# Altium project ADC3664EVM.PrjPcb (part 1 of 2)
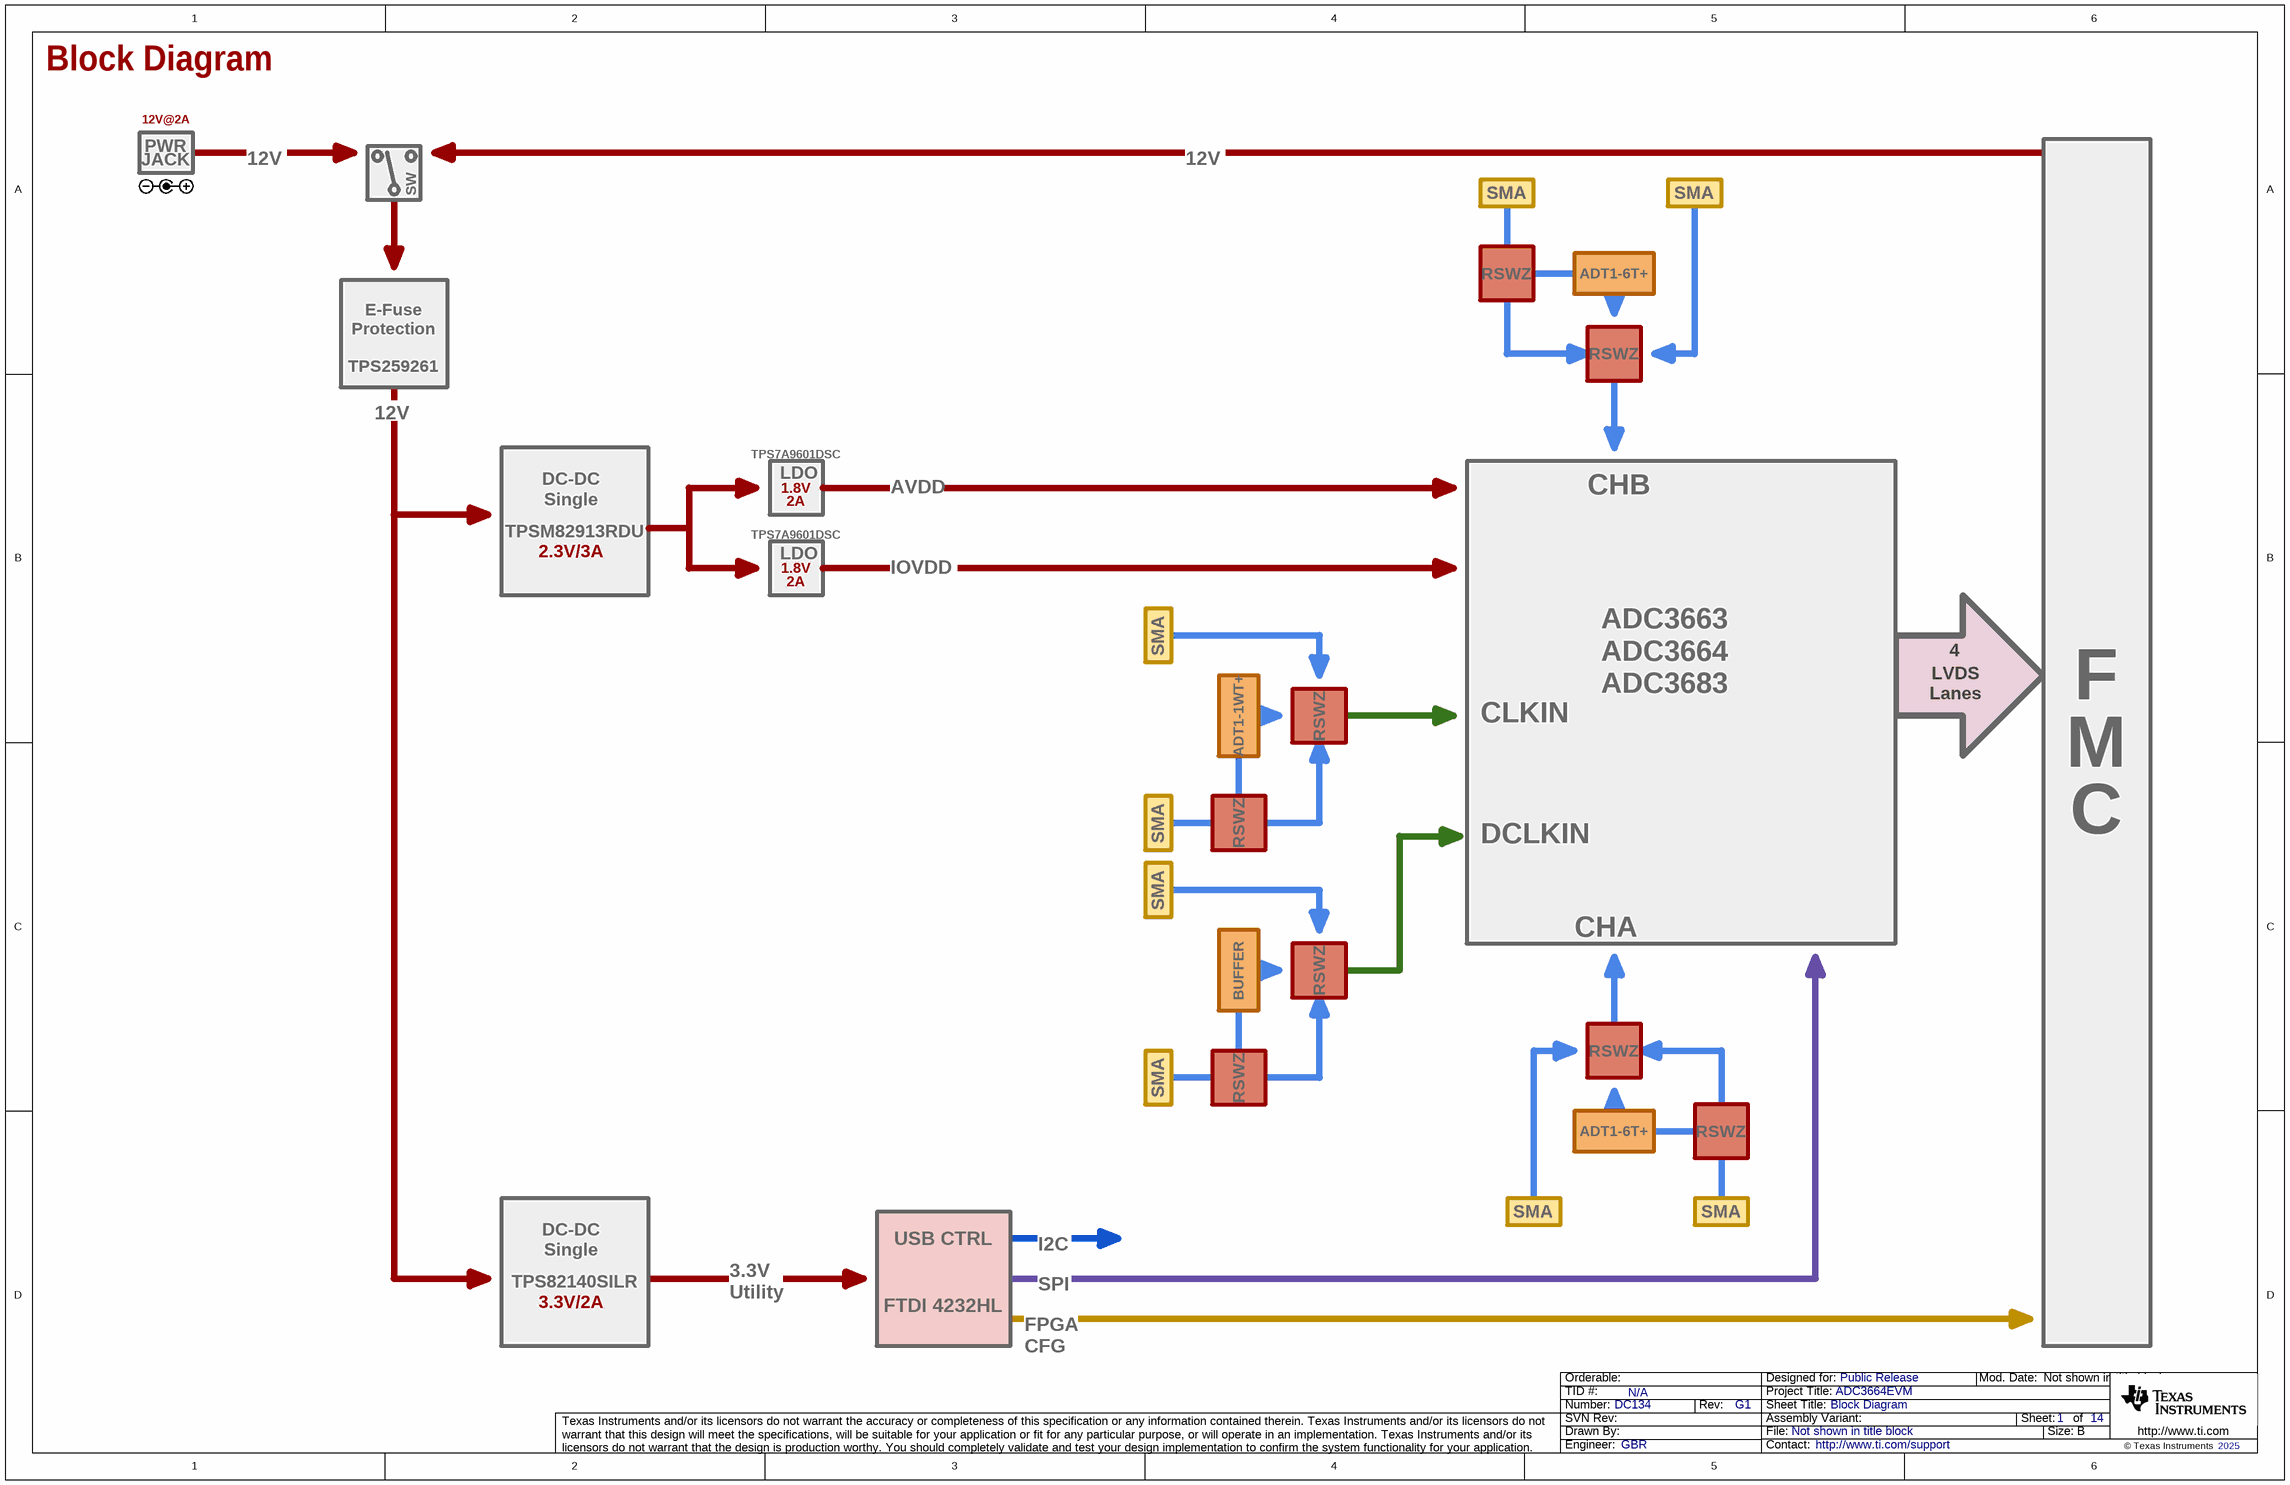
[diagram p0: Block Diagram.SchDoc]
TID: N/A; TechSupport: http://www.ti.com/support; SCH_Rev: G1; PRJ_Title: ADC3664EVM; PRJ_Number: DC134; PRJ_Engineer: GBR; PRJ_Customer: Public Release; PCB_Rev: G1; PCB_Layout: GBR; CopyrightYear: 2025
14 sheets, 374 parts. Net scope: flat (ports and power ports of the same name join across sheets).
Board file: ADC3664EVM.PcbDoc
Sheets:
  Block Diagram.SchDoc
  12V Input, Efuse and 3p3V Utility.SchDoc
  Power DC-DC.SchDoc
  Power LDO.SchDoc
  Power Sense ADC.SchDoc
  USB Control FTDI.SchDoc
  Comms LVL Shift and MUX.SchDoc
  CLK and DCLKIN.SchDoc
  ADC Inputs.SchDoc
  DUT IO.SchDoc
  FMC+ Sections A-E.SchDoc
  FMC+ Sections F-H, J, K.SchDoc
  Hardware & Mechanicals.SchDoc
  Revision History.SchDoc

## Sheet Block Diagram.SchDoc: Block Diagram
size 431 x 279 mm; Date: Not shown in title block; ApprovedBy: Not shown in title block; CheckedBy: Not shown in title block; Author: Not shown in title block; CompanyName: Not shown in title block; Engineer: Not shown in title block; Organization: Not shown in title block; Address1: Not shown in title block; Address2: Not shown in title block; Address3: Not shown in title block; Address4: Not shown in title block; DocumentNumber: 1; Revision: Use project parameter SCH_Rev; SheetNumber: 1; SheetTotal: 14; PageSetup: Record=PageOptions¦CenterHorizontal=True¦CenterVertical=True¦PrintScale=1.00¦XCorrection=1.00¦YCorrection=1.00¦PrintKind=0¦BorderSize=5000000¦LeftOffset=0¦BottomOffset=0¦Orientation=2¦PaperLength=1000¦PaperWidth=1000¦Scale=100¦PaperSource=15¦PrintQuality=600¦MediaType=1¦DitherType=10¦PaperKind=Letter¦PrintScaleMode=1

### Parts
(Parts that share a designator on the sheet are numbered #1, #2 ... from top to bottom, then left to right.)
*#1  SMA  (graphical)
*#2  SMA  (graphical)
*#3  PartNum: RSWZ  (hidden comment: R-SWIZZLE)  (graphical)
*#4  PartNum: ADT1-6T+  (hidden comment: Balun)  (graphical)
*#5  PartNum: RSWZ  (hidden comment: R-SWIZZLE)  (graphical)
*#6  A_Value: 2A  V_Value: 1.8V  PartNum: TPS7A9601DSC  (hidden comment: LDO)  (graphical)
*#7  Limits: 2.3V/3A  PartNum: TPSM82913RDU  (hidden comment: DC-DC Single)  (graphical)
*#8  A_Value: 2A  V_Value: 1.8V  PartNum: TPS7A9601DSC  (hidden comment: LDO)  (graphical)
*#9  SMA  (graphical)
*#10  # Lanes: 4  (hidden comment: LVDS Lanes)  (graphical)
*#11  PartNum: ADT1-1WT+  (hidden comment: Balun)  (graphical)
*#12  PartNum: RSWZ  (hidden comment: R-SWIZZLE)  (graphical)
*#13  FMC  (value not drawn)  (graphical)
*#14  SMA  (graphical)
*#15  PartNum: RSWZ  (hidden comment: R-SWIZZLE)  (graphical)
*#16  SMA  (graphical)
*#17  PartNum: BUFFER  (hidden comment: Balun)  (graphical)
*#18  PartNum: RSWZ  (hidden comment: R-SWIZZLE)  (graphical)
*#19  PartNum: RSWZ  (hidden comment: R-SWIZZLE)  (graphical)
*#20  SMA  (graphical)
*#21  PartNum: RSWZ  (hidden comment: R-SWIZZLE)  (graphical)
*#22  PartNum: ADT1-6T+  (hidden comment: Balun)  (graphical)
*#23  PartNum: RSWZ  (hidden comment: R-SWIZZLE)  (graphical)
*#24  SMA  (graphical)
*#25  SMA  (graphical)
*#26  Limits: 3.3V/2A  PartNum: TPS82140SILR  (hidden comment: DC-DC Single)  (graphical)
*#27  FTDI 4232HL  (value not drawn)  (graphical)
*?#1  PartNum: 12V@2A  (hidden comment: Power Jack)  (graphical)
*?#2  SWITCH  (value not drawn)  (graphical)
*?#3  E-Fuse  (value not drawn)  (graphical)

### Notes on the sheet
- 12V
- AVDD
- CHB
- IOVDD
- ADC3663
  ADC3664
  ADC3683
- CLKIN
- DCLKIN
- CHA
- 3.3V
  Utility
- I2C
- SPI
- FPGA
  CFG

## Sheet 12V Input, Efuse and 3p3V Utility.SchDoc: 12V Input & 3.3V Utility
size 431 x 279 mm; Date: Not shown in title block; ApprovedBy: Not shown in title block; CheckedBy: Not shown in title block; Author: Not shown in title block; CompanyName: Not shown in title block; Engineer: Not shown in title block; Organization: Not shown in title block; Address1: Not shown in title block; Address2: Not shown in title block; Address3: Not shown in title block; Address4: Not shown in title block; DocumentNumber: 1; Revision: Use project parameter SCH_Rev; SheetNumber: 2; SheetTotal: 14; PageSetup: Record=PageOptions¦CenterHorizontal=True¦CenterVertical=True¦PrintScale=1.00¦XCorrection=1.00¦YCorrection=1.00¦PrintKind=0¦BorderSize=5000000¦LeftOffset=0¦BottomOffset=0¦Orientation=2¦PaperLength=1000¦PaperWidth=1000¦Scale=100¦PaperSource=15¦PrintQuality=600¦MediaType=1¦DitherType=10¦PaperKind=Letter¦PrintScaleMode=1
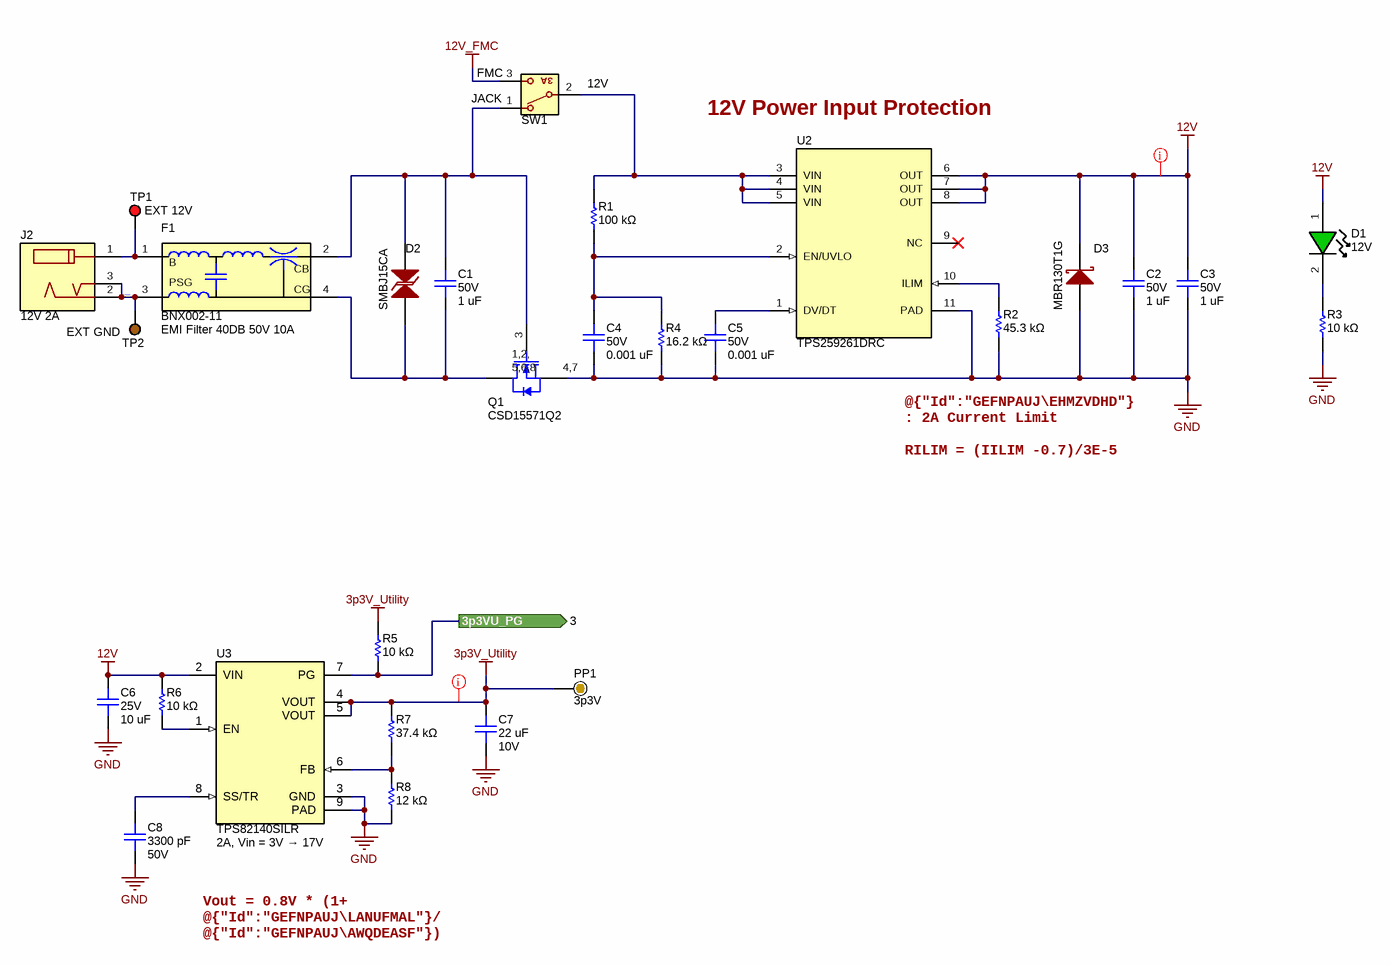
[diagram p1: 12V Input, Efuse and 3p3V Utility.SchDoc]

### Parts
C1  value 1 uF  Voltage - Rated: 50V  [0805L_cap]  (hidden comment: C2012X7R1H105K125AB)
C2  value 1 uF  Voltage - Rated: 50V  [0805L_cap]  (hidden comment: C2012X7R1H105K125AB)
C3  value 1 uF  Voltage - Rated: 50V  [0805L_cap]  (hidden comment: C2012X7R1H105K125AB)
C4  value 0.001 uF  Voltage - Rated: 50V  [0603L_cap]  (hidden comment: CGA3E2X7R1H102K080AA)
C5  value 0.001 uF  Voltage - Rated: 50V  [0603L_cap]  (hidden comment: CGA3E2X7R1H102K080AA)
C6  value 10 uF  Voltage - Rated: 25V  [0805L_cap]  (hidden comment: C2012X7S1E106K125AC)
C7  value 22 uF  Voltage - Rated: 10V  [0805L_cap]  (hidden comment: C2012X7S1A226M125AC)
C8  value 3300 pF  Voltage - Rated: 50V  [0402L_cap]  (hidden comment: CGA2B2X7R1H332K050BA)
D1  Text1: 12V  [LED_LTST-C190-Green]  (hidden comment: LTST-C191TGKT)
D2  SMBJ15CA  [SMBJ15CA]
D3  MBR130T1G  [SOD-123]
F1  BNX002-11  Text1: EMI Filter 40DB 50V 10A  [FIL_BNX002-11]
J2  Text1: 12V 2A  [RAPC722X]  (hidden comment: RAPC722X)
PP1  Text1: 3p3V  [ProbePoint_TH_40mil]  (hidden comment: Probe Point)  (no BOM)
Q1  CSD15571Q2  [DQK0006C]
R1  value 100 kΩ  [0402L]  (hidden comment: ERA-2AED104X)
R2  value 45.3 kΩ  [0402L]  (hidden comment: ERJ-2RKF4532X)
R3  value 10 kΩ  [0805L]  (hidden comment: ERJ-HP6F1002V)
R4  value 16.2 kΩ  [0402L]  (hidden comment: ERA-2AEB1622X)
R5  value 10 kΩ  [0402L]  (hidden comment: ERA-2AEB103X)
R6  value 10 kΩ  [0402L]  (hidden comment: ERA-2AEB103X)
R7  value 37.4 kΩ  [0402L]  (hidden comment: ERA-2AEB3742X)
R8  value 12 kΩ  [0402L]  (hidden comment: ERJ-2RKF1202X)
SW1  Text1: JACK  Text2: 12V  Text3: FMC  [500ASSP1M2QE]  (hidden comment: 500ASSP1M2QE)
TP1  Text1: EXT 12V  [Keystone5010]  (hidden comment: 5010)
TP2  Text1: EXT GND  [Keystone5125]  (hidden comment: 5125)
U2  TPS259261DRC  [DRC0010J]
U3  TPS82140SILR  Text1: 2A, Vin = 3V → 17V  [SIL0008D]

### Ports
3p3VU_PG (out, see 3)

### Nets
3p3V_Utility: C7.2 PP1.1 R5.2 R7.2 U3.4(VOUT) U3.5(VOUT)
12V: C2.2 C3.2 C6.2 D1.1(A) D3.1(K) R6.2 U2.6(OUT) U2.7(OUT) U2.8(OUT) U3.2(VIN)
12V_FMC: SW1.3
GND: C2.1 C3.1 C4.1 C5.1 C6.1 C7.1 C8.1 D3.2(A) Q1.4,7(S) R2.1 R3.1 R4.1 R8.1 U2.11(PAD) U3.3(GND) U3.9(PAD)
3p3VU_PG: R5.1 U3.7(PG) ; port 3p3VU_PG
EXTGND: F1.3(PSG) J2.2 J2.3 TP2.1
NetC1_1: C1.1 D2.2 F1.2(CB) Q1.3(G) SW1.1
NetC1_2: C1.2 D2.1 F1.4(CG) Q1.1,2,5,6,8(D)
NetC4_2: C4.2 R1.1 R4.2 U2.2(EN/UVLO)
NetC5_2: C5.2 U2.1(DV/DT)
NetC8_2: C8.2 U3.8(SS/TR)
NetD1_2: D1.2(K) R3.2
NetF1_1: F1.1(B) J2.1 TP1.1
NetR1_2: R1.2 SW1.2(COMM) U2.3(VIN) U2.4(VIN) U2.5(VIN)
NetR2_2: R2.2 U2.10(ILIM)
NetR6_1: R6.1 U3.1(EN)
NetR7_1: R7.1 R8.2 U3.6(FB)

Not connected (* = marked no-connect by the designer): U2 9(NC)*

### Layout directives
net class Power; net class GenPwr: 3p3V_Utility, 12V

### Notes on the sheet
- 12V Power Input Protection
- @{"Id":"GEFNPAUJ\EHMZVDHD"} : 2A Current Limit
  RILIM = (IILIM -0.7)/3E-5
- Vout = 0.8V * (1+ @{"Id":"GEFNPAUJ\LANUFMAL"}/ @{"Id":"GEFNPAUJ\AWQDEASF"})
  Vout = 3.3V

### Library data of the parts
C1-C3 = capcc02687: CAP CER 1UF 50V X7R 0805; Manufacturer: TDK Corporation; CompType: Capacitor Ceramic; Tolerance: ±10%; SizeX_mm: 2; SizeY_mm: 1.25; SizeZ_mm: 1.45
C4 C5 = capcc03751: CAP CER 1000PF 50V X7R 0603; Manufacturer: TDK Corporation; CompType: Capacitor Ceramic; Tolerance: ±10%; SizeX_mm: 1.6; SizeY_mm: 0.8; SizeZ_mm: 0.9
C6 = capcc03511: CAP CER 10UF 25V X7S 0805; Manufacturer: TDK Corporation; CompType: Capacitor Ceramic; Tolerance: ±10%; SizeX_mm: 2; SizeY_mm: 1.25; SizeZ_mm: 1.5
C7 = capcc09395: CAP CER 22UF 10V X7S 0805; Manufacturer: TDK Corporation; CompType: Capacitor Ceramic; Tolerance: ±20%; SizeX_mm: 2; SizeY_mm: 1.25; SizeZ_mm: 1.45
C8 = capcc04738: CAP CER 3300PF 50V X7R 0402; Manufacturer: TDK Corporation; CompType: Capacitor Ceramic; Tolerance: ±10%; SizeX_mm: 1; SizeY_mm: 0.5; SizeZ_mm: 0.55
D1 = cmp00247: LED GREEN CLEAR CHIP SMD; Manufacturer: Lite-On Inc.; Current Rating (Amps): 20mA; Voltage - Forward (Vf) (Typ): 3.2V; SizeX_mm: 1.6; SizeY_mm: 0.8; SizeZ_mm: 0.65
D2 = cmp00440: 24.4V Clamp 24.6A Ipp Tvs Diode; Manufacturer: Littlefuse; CompType: Diode TVS
D3 = cmp00438: DIODE SCHOTTKY 30V 1A SOD123; Manufacturer: Onsemi; Alt PartNumber: RB160M-30TR; Alt Manufacturer: Rohm Semiconductor
F1 = cmp00325: EMI Filter Circuits 40 DB 50V 10A; Manufacturer: Murata Electronics
J2 = cmp00022: Power Jack, mini, 2.1mm OD, R/A, TH; Manufacturer: Switchcraft
PP1 = Probe Point: Probe Point that can be used in lue of a test point; UniqueID: cmp00025
Q1 = cmp00159: MOSFET, N-CH, 20 V, 10 A; Manufacturer: Texas Instruments; CompType: FET
R1 = RSMD040200361: RES SMD 100K OHM 0.5% 1/16W 0402; Manufacturer: Panasonic Electronic Components; CompType: Resistor SMD; Power (Watts): 0.063W, 1/16W; Temperature Coefficient: ±25ppm/°C; SizeX_mm: 1; SizeY_mm: 0.5; SizeZ_mm: 0.4
R2 = RSMD040202774: RES SMD 45.3K OHM 1% 1/10W 0402; Manufacturer: Panasonic Electronic Components; CompType: Resistor SMD; Power (Watts): 0.1W, 1/10W; Temperature Coefficient: ±100ppm/°C; SizeX_mm: 1; SizeY_mm: 0.5; SizeZ_mm: 0.4
R3 = RSMD080502076: RES 10K OHM 1% 1/2W 0805; Manufacturer: Panasonic Electronic Components; CompType: Resistor SMD; Power (Watts): 0.5W, 1/2W; Temperature Coefficient: ±100ppm/°C; SizeX_mm: 2; SizeY_mm: 1.25; SizeZ_mm: 0.7
R4 = RSMD040200899: RES SMD 16.2KOHM 0.1% 1/16W 0402; Manufacturer: Panasonic Electronic Components; CompType: Resistor SMD; Power (Watts): 0.063W, 1/16W; Temperature Coefficient: ±25ppm/°C; SizeX_mm: 1; SizeY_mm: 0.5; SizeZ_mm: 0.4
R5 R6 = RSMD040200315: RES SMD 10K OHM 0.1% 1/16W 0402; Manufacturer: Panasonic Electronic Components; CompType: Resistor SMD; Power (Watts): 0.063W, 1/16W; Temperature Coefficient: ±25ppm/°C; SizeX_mm: 1; SizeY_mm: 0.5; SizeZ_mm: 0.4
R7 = RSMD040202418: RES SMD 37.4KOHM 0.1% 1/16W 0402; Manufacturer: Panasonic Electronic Components; CompType: Resistor SMD; Power (Watts): 0.063W, 1/16W; Temperature Coefficient: ±25ppm/°C; SizeX_mm: 1; SizeY_mm: 0.5; SizeZ_mm: 0.4
R8 = RSMD040200519: RES SMD 12K OHM 1% 1/10W 0402; Manufacturer: Panasonic Electronic Components; CompType: Resistor SMD; Power (Watts): 0.1W, 1/10W; Temperature Coefficient: ±100ppm/°C; SizeX_mm: 1; SizeY_mm: 0.5; SizeZ_mm: 0.4
SW1 = cmp00460: SWITCH SLIDE SPDT 3A 120V; Manufacturer: E-Switch; Pitch (mm): 2.54
TP1 = cmp00040: Test Point, Multipurpose, Red, TH; Manufacturer: Keystone
TP2 = cmp00047: Test Point, Multipurpose, Brown, TH; Manufacturer: Keystone
U2 = cmp00157: 12V, 5A, 30mΩ eFuse with Adjustable +/-15% Accurate Current Limit, DRC0010J (VSON-10); Manufacturer: Texas Instruments
U3 = TPS82140SILR: 17V Input 2A Synchronous Step-Down Converter MicroSiP Module With Integrated Inductor, SIL0008D (uSIP-8); Manufacturer: Texas Instruments; Alternate PartNumber: TPS82140SILT; CompType: Switcher

## Sheet Power DC-DC.SchDoc: DC/DC regulator
size 431 x 279 mm; Date: Not shown in title block; ApprovedBy: Not shown in title block; CheckedBy: Not shown in title block; Author: Not shown in title block; CompanyName: Not shown in title block; Engineer: Not shown in title block; Organization: Not shown in title block; Address1: Not shown in title block; Address2: Not shown in title block; Address3: Not shown in title block; Address4: Not shown in title block; DocumentNumber: 1; Revision: Use project parameter SCH_Rev; SheetNumber: 3; SheetTotal: 14; PageSetup: Record=PageOptions¦CenterHorizontal=True¦CenterVertical=True¦PrintScale=1.00¦XCorrection=1.00¦YCorrection=1.00¦PrintKind=0¦BorderSize=5000000¦LeftOffset=0¦BottomOffset=0¦Orientation=2¦PaperLength=1000¦PaperWidth=1000¦Scale=100¦PaperSource=15¦PrintQuality=600¦MediaType=1¦DitherType=10¦PaperKind=Letter¦PrintScaleMode=1
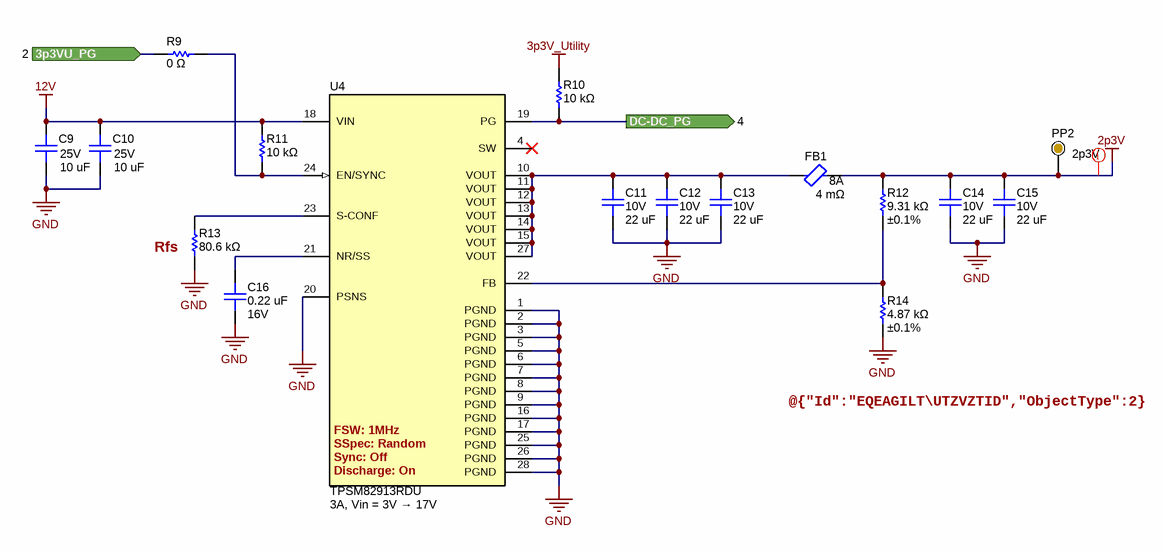
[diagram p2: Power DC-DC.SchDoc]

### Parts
C9  value 10 uF  Voltage - Rated: 25V  [0805L_cap]  (hidden comment: C2012X7S1E106K125AC)
C10  value 10 uF  Voltage - Rated: 25V  [0805L_cap]  (hidden comment: C2012X7S1E106K125AC)
C11  value 22 uF  Voltage - Rated: 10V  [0805L_cap]  (hidden comment: C2012X7S1A226M125AC)
C12  value 22 uF  Voltage - Rated: 10V  [0805L_cap]  (hidden comment: C2012X7S1A226M125AC)
C13  value 22 uF  Voltage - Rated: 10V  [0805L_cap]  (hidden comment: C2012X7S1A226M125AC)
C14  value 22 uF  Voltage - Rated: 10V  [0805L_cap]  (hidden comment: C2012X7S1A226M125AC)
C15  value 22 uF  Voltage - Rated: 10V  [0805L_cap]  (hidden comment: C2012X7S1A226M125AC)
C16  value 0.22 uF  Voltage - Rated: 16V  [0402L_cap]  (hidden comment: CGA2B1X5R1C224M050BC)
FB1  DCR: 4 mΩ  Current: 8A  [0603L]  (hidden comment: BLE18PS080SN1D)
PP2  Text1: 2p3V  [ProbePoint_TH_40mil]  (hidden comment: Probe Point)  (no BOM)
R9  value 0 Ω  [0402L]  (hidden comment: ERJ-U020R00X)
R10  value 10 kΩ  [0402L]  (hidden comment: ERA-2AEB103X)
R11  value 10 kΩ  [0402L]  (hidden comment: ERJ-2RKF1002X)
R12  value 9.31 kΩ  Tolerance: ±0.1%  [0402L]  (hidden comment: ERA-2AEB9311X)
R13  value 80.6 kΩ  [0402L]  (hidden comment: ERJ-2RKF8062X)
R14  value 4.87 kΩ  Tolerance: ±0.1%  [0402L]  (hidden comment: ERA-2AEB4871X)
U4  TPSM82913RDU  Text1: 3A, Vin = 3V → 17V  Discharge: On  Sync: Off  SSpec: Random  FSW: 1MHz  [RDU0028A]

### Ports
3p3VU_PG (in, see 2), DC-DC_PG (out, see 4)

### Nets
2p3V: C14.2 C15.2 FB1.2 PP2.1 R12.2
3p3V_Utility: R10.2
12V: C9.2 C10.2 R11.2 U4.18(VIN)
GND: C9.1 C10.1 C11.1 C12.1 C13.1 C14.1 C15.1 C16.2 R13.1 R14.1 U4.1(PGND) U4.2(PGND) U4.3(PGND) U4.5(PGND) U4.6(PGND) U4.7(PGND) U4.8(PGND) U4.9(PGND) U4.16(PGND) U4.17(PGND) U4.20(PSNS) U4.25(PGND) U4.26(PGND) U4.28(PGND)
3p3VU_PG: R9.2 ; port 3p3VU_PG
DC-DC_PG: R10.1 U4.19(PG) ; port DC-DC_PG
NetC11_2: C11.2 C12.2 C13.2 FB1.1 U4.10(VOUT) U4.11(VOUT) U4.12(VOUT) U4.13(VOUT) U4.14(VOUT) U4.15(VOUT) U4.27(VOUT)
NetC16_1: C16.1 U4.21(NR/SS)
NetR9_1: R9.1 R11.1 U4.24(EN/SYNC)
NetR12_1: R12.1 R14.2 U4.22(FB)
NetR13_2: R13.2 U4.23(S-CONF)

Not connected (* = marked no-connect by the designer): U4 4(SW)*

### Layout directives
net class Power; net class GenPwr: 2p3V

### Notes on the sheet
- (near R13) Rfs
- @{"Id":"EQEAGILT\UTZVZTID","ObjectType":2} = @{"Id":"EQEAGILT\NLLUWDBR","ObjectType":2} *(VOUT/0.8 -1)

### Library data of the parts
C9 C10 = capcc03511: as C6 on sheet 12V Input, Efuse and 3p3V Utility
C11-C15 = capcc09395: as C7 on sheet 12V Input, Efuse and 3p3V Utility
C16 = capcc01693: CAP CER 0.22UF 16V X5R 0402; Manufacturer: TDK Corporation; CompType: Capacitor Ceramic; Tolerance: ±20%; SizeX_mm: 1; SizeY_mm: 0.5; SizeZ_mm: 0.55
FB1 = dcp00004: 8.5 Ohms @ 100 MHz 1 Power Line Ferrite Bead 0603 (1608 Metric) 8A 4mOhm; Manufacturer: Murata; Impedance: 8.5 Ω; SizeX_mm: 1.6; SizeY_mm: 0.8
PP2 = cmp00025: Probe Point that can be used in lue of a test point
R9 = RSMD040200004: RES 0 OHM JUMPER 0402 SMD; Manufacturer: Panasonic Electronic Components; CompType: Resistor SMD; Power (Watts): 0.1W, 1/10W; Temperature Coefficient: -100/ +600ppm/°C; SizeX_mm: 1; SizeY_mm: 0.5; SizeZ_mm: 0.4
R10 = RSMD040200315: as R5 on sheet 12V Input, Efuse and 3p3V Utility
R11 = RSMD040200314: RES SMD 10K OHM 1% 1/10W 0402; Manufacturer: Panasonic Electronic Components; CompType: Resistor SMD; Power (Watts): 0.1W, 1/10W; Temperature Coefficient: ±100ppm/°C; SizeX_mm: 1; SizeY_mm: 0.5; SizeZ_mm: 0.4
R12 = RSMD040203923: RES SMD 9.31KOHM 0.1% 1/16W 0402; Manufacturer: Panasonic Electronic Components; CompType: Resistor SMD; Power (Watts): 0.063W, 1/16W; Temperature Coefficient: ±25ppm/°C; SizeX_mm: 1; SizeY_mm: 0.5; SizeZ_mm: 0.4
R13 = RSMD040203748: RES SMD 80.6K OHM 1% 1/10W 0402; Manufacturer: Panasonic Electronic Components; CompType: Resistor SMD; Power (Watts): 0.1W, 1/10W; Temperature Coefficient: ±100ppm/°C; SizeX_mm: 1; SizeY_mm: 0.5; SizeZ_mm: 0.4
R14 = RSMD040202615: RES SMD 4.87KOHM 0.1% 1/16W 0402; Manufacturer: Panasonic Electronic Components; CompType: Resistor SMD; Power (Watts): 0.063W, 1/16W; Temperature Coefficient: ±25ppm/°C; SizeX_mm: 1; SizeY_mm: 0.5; SizeZ_mm: 0.4
U4 = cmp00201: 3-V to 17-V, 3-A Low-Noise and Low-Ripple Buck Power Module with Integrated Ferrite Bead Filter Compensation; Part Number: TPSM82913RDUR; Manufacturer: Texas Instruments; Switching Frequency: 1/2.2MHz; Max Duty Cycle: 100%; Output Voltage: 0.8-5.5V; Standoff Height: 0mm; CompType: Switcher; Number Of Outputs: 1; Max Supply Voltage: 17V; AEC Category: Q200; TJmax_C: +125°C; Nominal Supply Current: 5mA; Output Type: AdjustableProgrammable; Min Supply Voltage: 3V; AEC Qualified: No

## Sheet Power LDO.SchDoc: LDOs
size 431 x 279 mm; Date: Not shown in title block; ApprovedBy: Not shown in title block; CheckedBy: Not shown in title block; Author: Not shown in title block; CompanyName: Not shown in title block; Engineer: Not shown in title block; Organization: Not shown in title block; Address1: Not shown in title block; Address2: Not shown in title block; Address3: Not shown in title block; Address4: Not shown in title block; DocumentNumber: 1; Revision: Use project parameter SCH_Rev; SheetNumber: 4; SheetTotal: 14; PageSetup: Record=PageOptions¦CenterHorizontal=True¦CenterVertical=True¦PrintScale=1.00¦XCorrection=1.00¦YCorrection=1.00¦PrintKind=0¦BorderSize=5000000¦LeftOffset=0¦BottomOffset=0¦Orientation=2¦PaperLength=1000¦PaperWidth=1000¦Scale=100¦PaperSource=15¦PrintQuality=600¦MediaType=1¦DitherType=10¦PaperKind=Letter¦PrintScaleMode=1
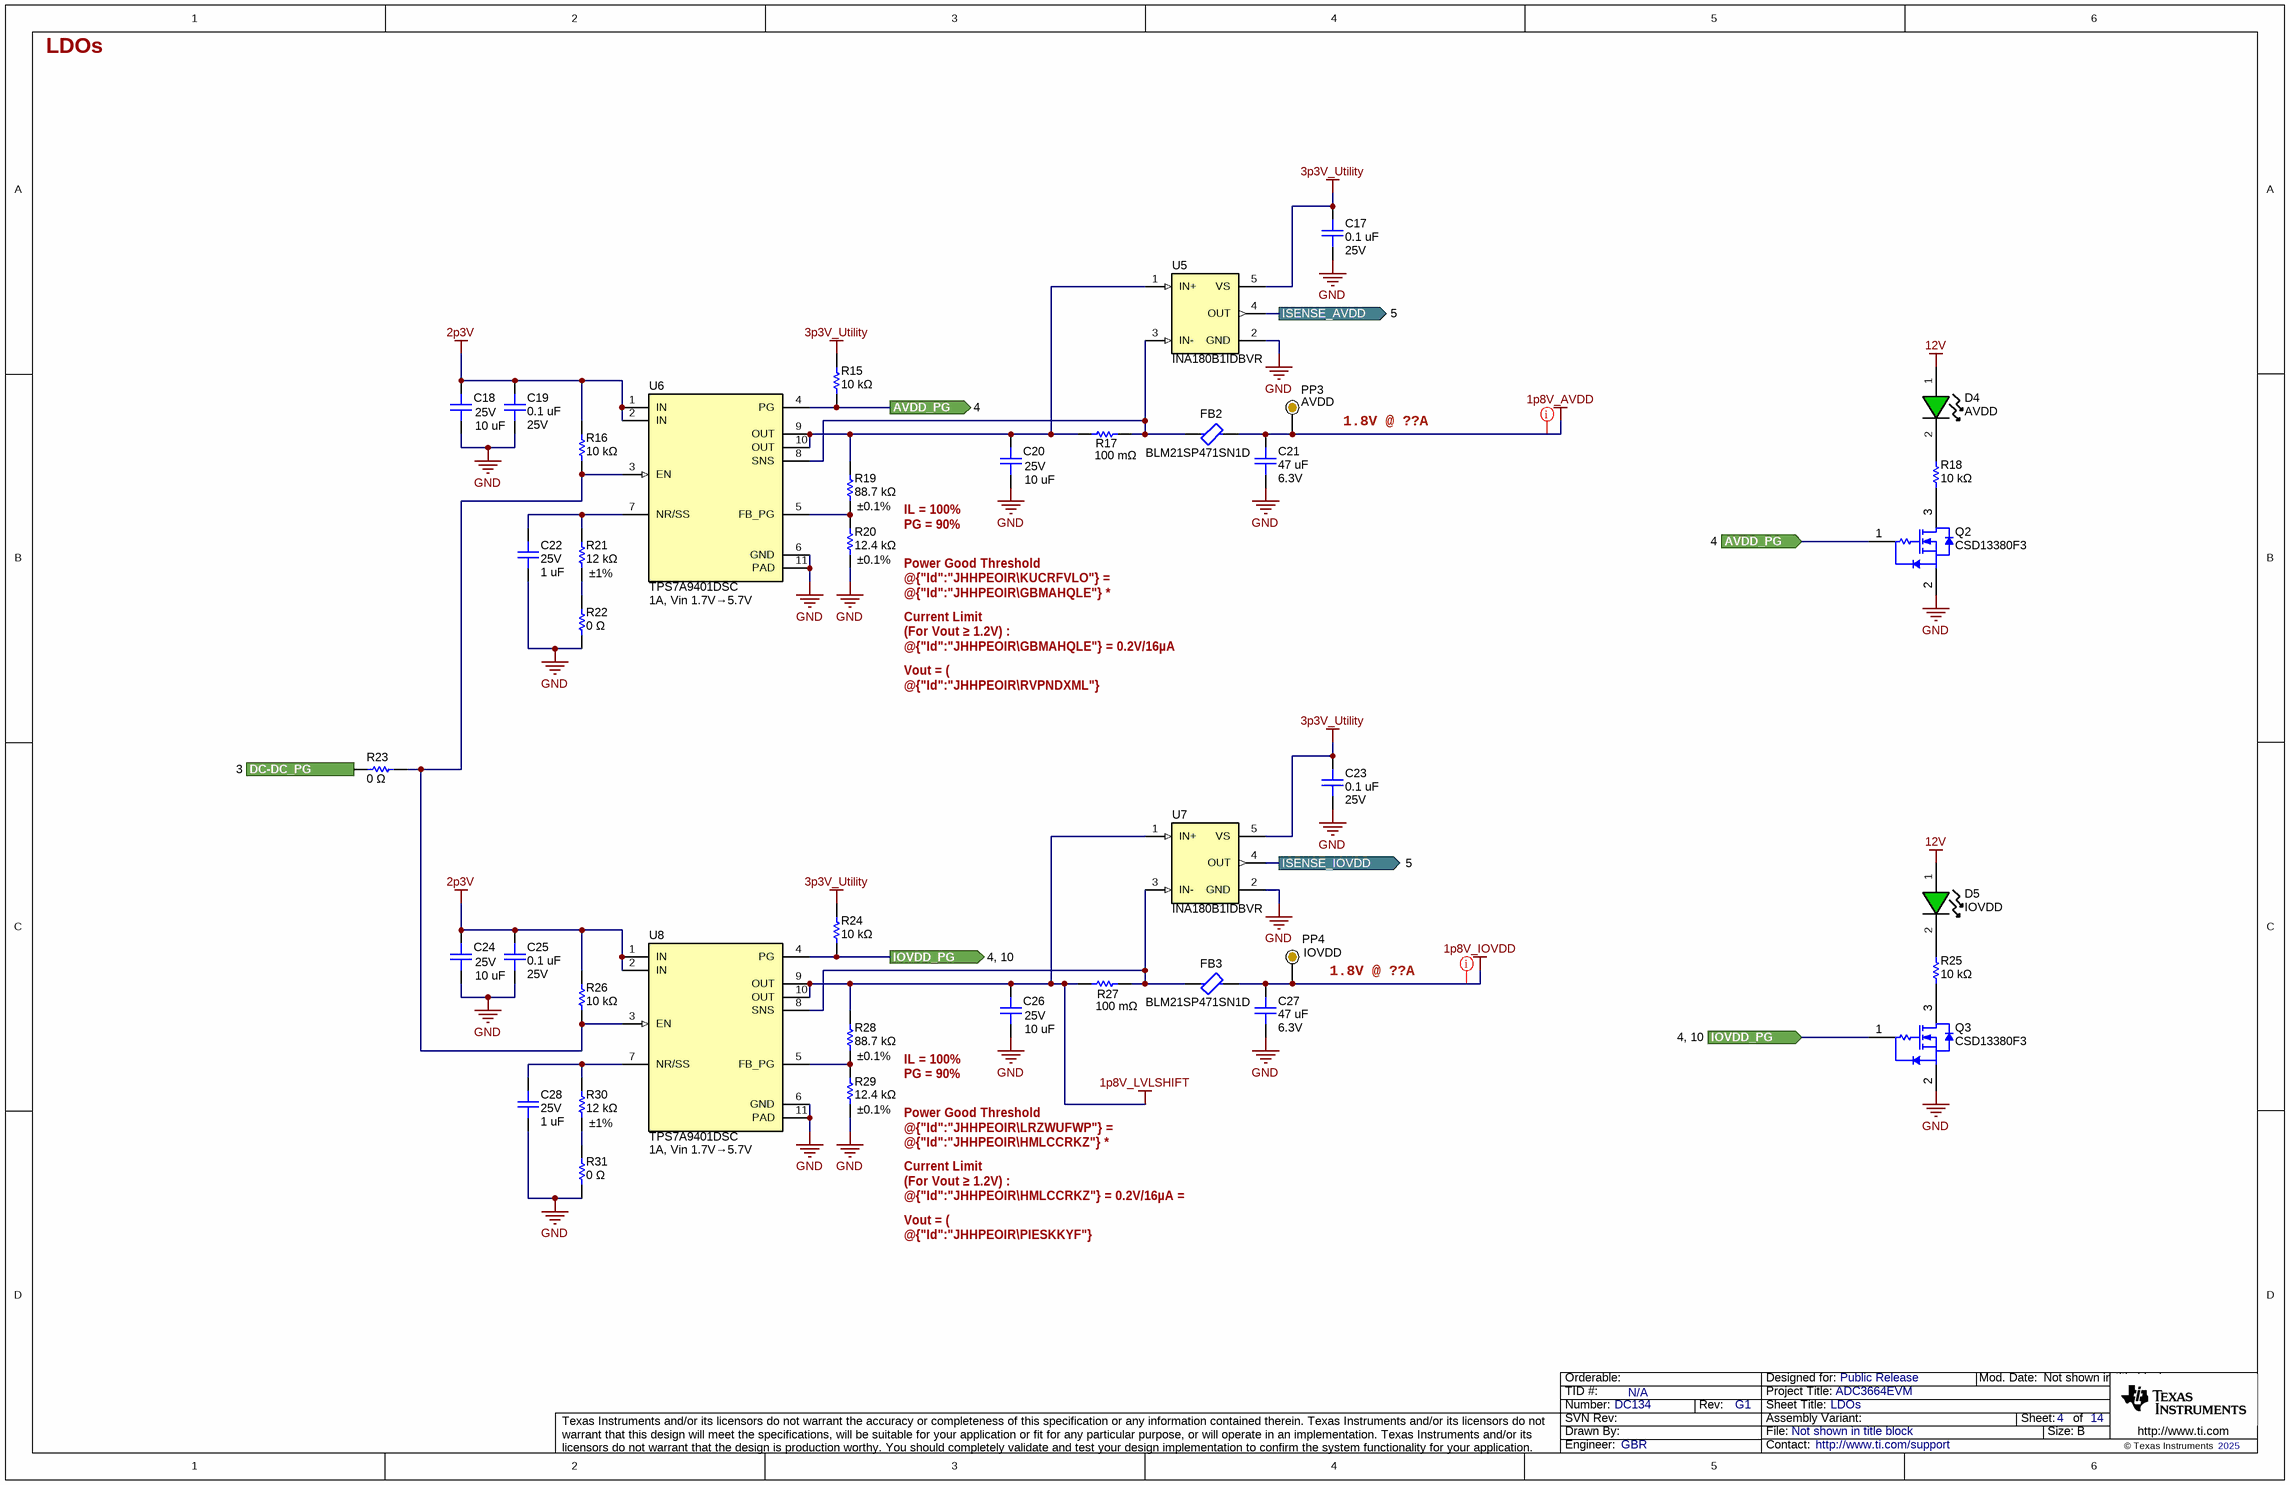
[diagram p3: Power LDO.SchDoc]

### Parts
C17  value 0.1 uF  Voltage - Rated: 25V  [0402L_cap]  (hidden comment: GRT155R71E104KE01J)
C18  value 10 uF  Voltage - Rated: 25V  [0805L_cap]  (hidden comment: C2012X7S1E106K125AC)
C19  value 0.1 uF  Voltage - Rated: 25V  [0402L_cap]  (hidden comment: GRT155R71E104KE01J)
C20  value 10 uF  Voltage - Rated: 25V  [0805L_cap]  (hidden comment: C2012X7S1E106K125AC)
C21  value 47 uF  Voltage - Rated: 6.3V  [0603L_cap]  (hidden comment: GRM188R60J476ME15D)
C22  value 1 uF  Voltage - Rated: 25V  [0402L_cap]  (hidden comment: C1005X5R1E105K050BC)
C23  value 0.1 uF  Voltage - Rated: 25V  [0402L_cap]  (hidden comment: GRT155R71E104KE01J)
C24  value 10 uF  Voltage - Rated: 25V  [0805L_cap]  (hidden comment: C2012X7S1E106K125AC)
C25  value 0.1 uF  Voltage - Rated: 25V  [0402L_cap]  (hidden comment: GRT155R71E104KE01J)
C26  value 10 uF  Voltage - Rated: 25V  [0805L_cap]  (hidden comment: C2012X7S1E106K125AC)
C27  value 47 uF  Voltage - Rated: 6.3V  [0603L_cap]  (hidden comment: GRM188R60J476ME15D)
C28  value 1 uF  Voltage - Rated: 25V  [0402L_cap]  (hidden comment: C1005X5R1E105K050BC)
D4  Text1: AVDD  [LED_LTST-C190-Green]  (hidden comment: LTST-C191TGKT)
D5  Text1: IOVDD  [LED_LTST-C190-Green]  (hidden comment: LTST-C191TGKT)
FB2  BLM21SP471SN1D  [0805L]
FB3  BLM21SP471SN1D  [0805L]
PP3  Text1: AVDD  [ProbePoint_TH_40mil]  (hidden comment: Probe Point)  (no BOM)
PP4  Text1: IOVDD  [ProbePoint_TH_40mil]  (hidden comment: Probe Point)  (no BOM)
Q2  CSD13380F3  [YJM0003A]
Q3  CSD13380F3  [YJM0003A]
R15  value 10 kΩ  [0402L]  (hidden comment: ERA-2AEB103X)
R16  value 10 kΩ  [0402L]  (hidden comment: ERJ-2RKF1002X)
R17  value 100 mΩ  [CCS0603FLxLxx]  (hidden comment: WSLP0603R1000FEA)
R18  value 10 kΩ  [0805L]  (hidden comment: ERJ-HP6F1002V)
R19  value 88.7 kΩ  Tolerance: ±0.1%  [0402L]  (hidden comment: RT0402BRD0788K7L)
R20  value 12.4 kΩ  Tolerance: ±0.1%  [0402L]  (hidden comment: ERA-2AEB1242X)
R21  value 12 kΩ  Tolerance: ±1%  [0402L]  (hidden comment: ERJ-2RKF1202X)
R22  value 0 Ω  [0402L]  (hidden comment: ERJ-U020R00X)
R23  value 0 Ω  [0402L]  (hidden comment: ERJ-U020R00X)
R24  value 10 kΩ  [0402L]  (hidden comment: ERA-2AEB103X)
R25  value 10 kΩ  [0805L]  (hidden comment: ERJ-HP6F1002V)
R26  value 10 kΩ  [0402L]  (hidden comment: ERJ-2RKF1002X)
R27  value 100 mΩ  [CCS0603FLxLxx]  (hidden comment: WSLP0603R1000FEA)
R28  value 88.7 kΩ  Tolerance: ±0.1%  [0402L]  (hidden comment: RT0402BRD0788K7L)
R29  value 12.4 kΩ  Tolerance: ±0.1%  [0402L]  (hidden comment: ERA-2AEB1242X)
R30  value 12 kΩ  Tolerance: ±1%  [0402L]  (hidden comment: ERJ-2RKF1202X)
R31  value 0 Ω  [0402L]  (hidden comment: ERJ-U020R00X)
U5  INA180B1IDBVR  [DBV0005A]
U6  TPS7A9401DSC  Text1: 1A, Vin 1.7V→5.7V  [DSC0010]
U7  INA180B1IDBVR  [DBV0005A]
U8  TPS7A9401DSC  Text1: 1A, Vin 1.7V→5.7V  [DSC0010]

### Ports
AVDD_PG (in, see 4), AVDD_PG (out, see 4), DC-DC_PG (in, see 3), IOVDD_PG (in, see 4, 10), IOVDD_PG (out, see 4, 10), ISENSE_AVDD (out, see 5), ISENSE_IOVDD (out, see 5)

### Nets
1p8V_AVDD: C21.2 FB2.2 PP3.1
1p8V_IOVDD: C27.2 FB3.2 PP4.1
1p8V_LVLSHIFT: C26.2 R27.1 R28.2 U7.1(IN+) U8.9(OUT) U8.10(OUT)
2p3V: C18.2 C19.2 C24.2 C25.2 R16.2 R26.2 U6.1(IN) U6.2(IN) U8.1(IN) U8.2(IN)
3p3V_Utility: C17.2 C23.2 R15.2 R24.2 U5.5(VS) U7.5(VS)
12V: D4.1(A) D5.1(A)
GND: C17.1 C18.1 C19.1 C20.1 C21.1 C22.1 C23.1 C24.1 C25.1 C26.1 C27.1 C28.1 Q2.2(S) Q3.2(S) R20.1 R22.1 R29.1 R31.1 U5.2(GND) U6.6(GND) U6.11(PAD) U7.2(GND) U8.6(GND) U8.11(PAD)
AVDD_PG: Q2.1(G) R15.1 U6.4(PG) ; port AVDD_PG
DC-DC_PG: R23.2 ; port DC-DC_PG
IOVDD_PG: Q3.1(G) R24.1 U8.4(PG) ; port IOVDD_PG
ISENSE_AVDD: U5.4(OUT) ; port ISENSE_AVDD
ISENSE_IOVDD: U7.4(OUT) ; port ISENSE_IOVDD
NetC20_2: C20.2 R17.1 R19.2 U5.1(IN+) U6.9(OUT) U6.10(OUT)
NetC22_2: C22.2 R21.2 U6.7(NR/SS)
NetC28_2: C28.2 R30.2 U8.7(NR/SS)
NetD4_2: D4.2(K) R18.2
NetD5_2: D5.2(K) R25.2
NetFB2_1: FB2.1 R17.2 U5.3(IN-) U6.8(SNS)
NetFB3_1: FB3.1 R27.2 U7.3(IN-) U8.8(SNS)
NetQ2_3: Q2.3(D) R18.1
NetQ3_3: Q3.3(D) R25.1
NetR16_1: R16.1 R23.1 R26.1 U6.3(EN) U8.3(EN)
NetR19_1: R19.1 R20.2 U6.5(FB_PG)
NetR21_1: R21.1 R22.2
NetR28_1: R28.1 R29.2 U8.5(FB_PG)
NetR30_1: R30.1 R31.2

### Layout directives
net class Power; net class DUTPwr: 1p8V_AVDD, 1p8V_IOVDD

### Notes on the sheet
- 1.8V @ ??A
- IL = 100%
  PG = 90%
- Power Good Threshold
  @{"Id":"JHHPEOIR\KUCRFVLO"} = @{"Id":"JHHPEOIR\GBMAHQLE"} * (VOUT/0.2*K-1)
  K = PG % Threshold
- Current Limit
  (For Vout ≥ 1.2V) : @{"Id":"JHHPEOIR\GBMAHQLE"} = 0.2V/16µA = 12.4k
- Vout = ( @{"Id":"JHHPEOIR\RVPNDXML"} + @{"Id":"JHHPEOIR\VYCEATNQ"} ) *150µA
  Vout = 1.8V
- (near PP4) 1.8V @ ??A
- Power Good Threshold
  @{"Id":"JHHPEOIR\LRZWUFWP"} = @{"Id":"JHHPEOIR\HMLCCRKZ"} * (VOUT/0.2*K-1)
  K = PG % Threshold
- Current Limit
  (For Vout ≥ 1.2V) : @{"Id":"JHHPEOIR\HMLCCRKZ"} = 0.2V/16µA = 12.4k
- Vout = ( @{"Id":"JHHPEOIR\PIESKKYF"} + @{"Id":"JHHPEOIR\BNWUTHKX"} ) *150µA
  Vout = 1.8V

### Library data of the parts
C17 C19 C23 C25 = capcc09401: CAP CER 0.1UF 25V X7R 0402; Manufacturer: Murata; CompType: Capacitor Ceramic; Tolerance: ±10%; SizeX_mm: 1; SizeY_mm: 0.5; SizeZ_mm: 0.7
C18 C20 C24 C26 = capcc03511: as C6 on sheet 12V Input, Efuse and 3p3V Utility
C21 C27 = GRM188R60J476ME15D: CAP CER 47UF 6.3V X5R 0603; Manufacturer: Murata; CompType: Capacitor Ceramic; Tolerance: ±20%; SizeX_mm: 1.6; SizeY_mm: 0.81; SizeZ_mm: 0.9
C22 C28 = capcc02750: CAP CER 1UF 25V X5R 0402; Manufacturer: TDK Corporation; CompType: Capacitor Ceramic; Tolerance: ±10%; SizeX_mm: 1; SizeY_mm: 0.5; SizeZ_mm: 0.55
D4 D5 = cmp00247: as D1 on sheet 12V Input, Efuse and 3p3V Utility
FB2 FB3 = dcp00579: FERRITEBEAD SMD Z100MHZ=470OHM 2; Manufacturer: Murata Electronics; Current: 2.5A; Impedance: 470 Ω
PP3 PP4 = Probe Point: as PP1 on sheet 12V Input, Efuse and 3p3V Utility
Q2 Q3 = CSD13380F3: MOSFET, N-CH, 12 V, 3.6 A, YJM0003A (PICOSTAR-3); Manufacturer: Texas Instruments; CompType: NMOS
R15 R24 = RSMD040200315: as R5 on sheet 12V Input, Efuse and 3p3V Utility
R16 R26 = RSMD040200314: as R11 on sheet Power DC-DC
R17 R27 = WSLP0603R1000FEA: RES 0.1 OHM 1% 2/5W 0603; Manufacturer: Vishay Dale; CompType: Resistor SMD Sense; Resistance: 3 mΩ; Power (Watts): 0.4W, 2/5W
R18 R25 = RSMD080502076: as R3 on sheet 12V Input, Efuse and 3p3V Utility
R19 R28 = RSMD040203878: RES SMD 88.7KOHM 0.1% 1/16W 0402; Manufacturer: Yageo; CompType: Resistor SMD; Power (Watts): 0.063W, 1/16W; Temperature Coefficient: ±25ppm/°C; SizeX_mm: 1; SizeY_mm: 0.5; SizeZ_mm: 0.4
R20 R29 = RSMD040200551: RES SMD 12.4KOHM 0.1% 1/16W 0402; Manufacturer: Panasonic Electronic Components; CompType: Resistor SMD; Power (Watts): 0.063W, 1/16W; Temperature Coefficient: ±25ppm/°C; SizeX_mm: 1; SizeY_mm: 0.5; SizeZ_mm: 0.4
R21 R30 = RSMD040200519: as R8 on sheet 12V Input, Efuse and 3p3V Utility
R22 R23 R31 = RSMD040200004: as R9 on sheet Power DC-DC
U5 U7 = INA180B1IDBVR: 26V, 350kHz current sense amplifier; Manufacturer: Texas Instruments; Alt PartNumber: INA180B1IDBVT; CompType: Current Amplifier
U6 U8 = cmp00169: 1-A, ultra-low noise, ultra-high PSRR, RF voltage regulator; Manufacturer: Texas Instruments; CompType: LDO

## Sheet Power Sense ADC.SchDoc: Sense ADC
size 431 x 279 mm; Date: Not shown in title block; ApprovedBy: Not shown in title block; CheckedBy: Not shown in title block; Author: Not shown in title block; CompanyName: Not shown in title block; Engineer: Not shown in title block; Organization: Not shown in title block; Address1: Not shown in title block; Address2: Not shown in title block; Address3: Not shown in title block; Address4: Not shown in title block; DocumentNumber: 1; Revision: Use project parameter SCH_Rev; SheetNumber: 5; SheetTotal: 14; PageSetup: Record=PageOptions¦CenterHorizontal=True¦CenterVertical=True¦PrintScale=1.00¦XCorrection=1.00¦YCorrection=1.00¦PrintKind=0¦BorderSize=5000000¦LeftOffset=0¦BottomOffset=0¦Orientation=2¦PaperLength=1000¦PaperWidth=1000¦Scale=100¦PaperSource=15¦PrintQuality=600¦MediaType=1¦DitherType=10¦PaperKind=Letter¦PrintScaleMode=1
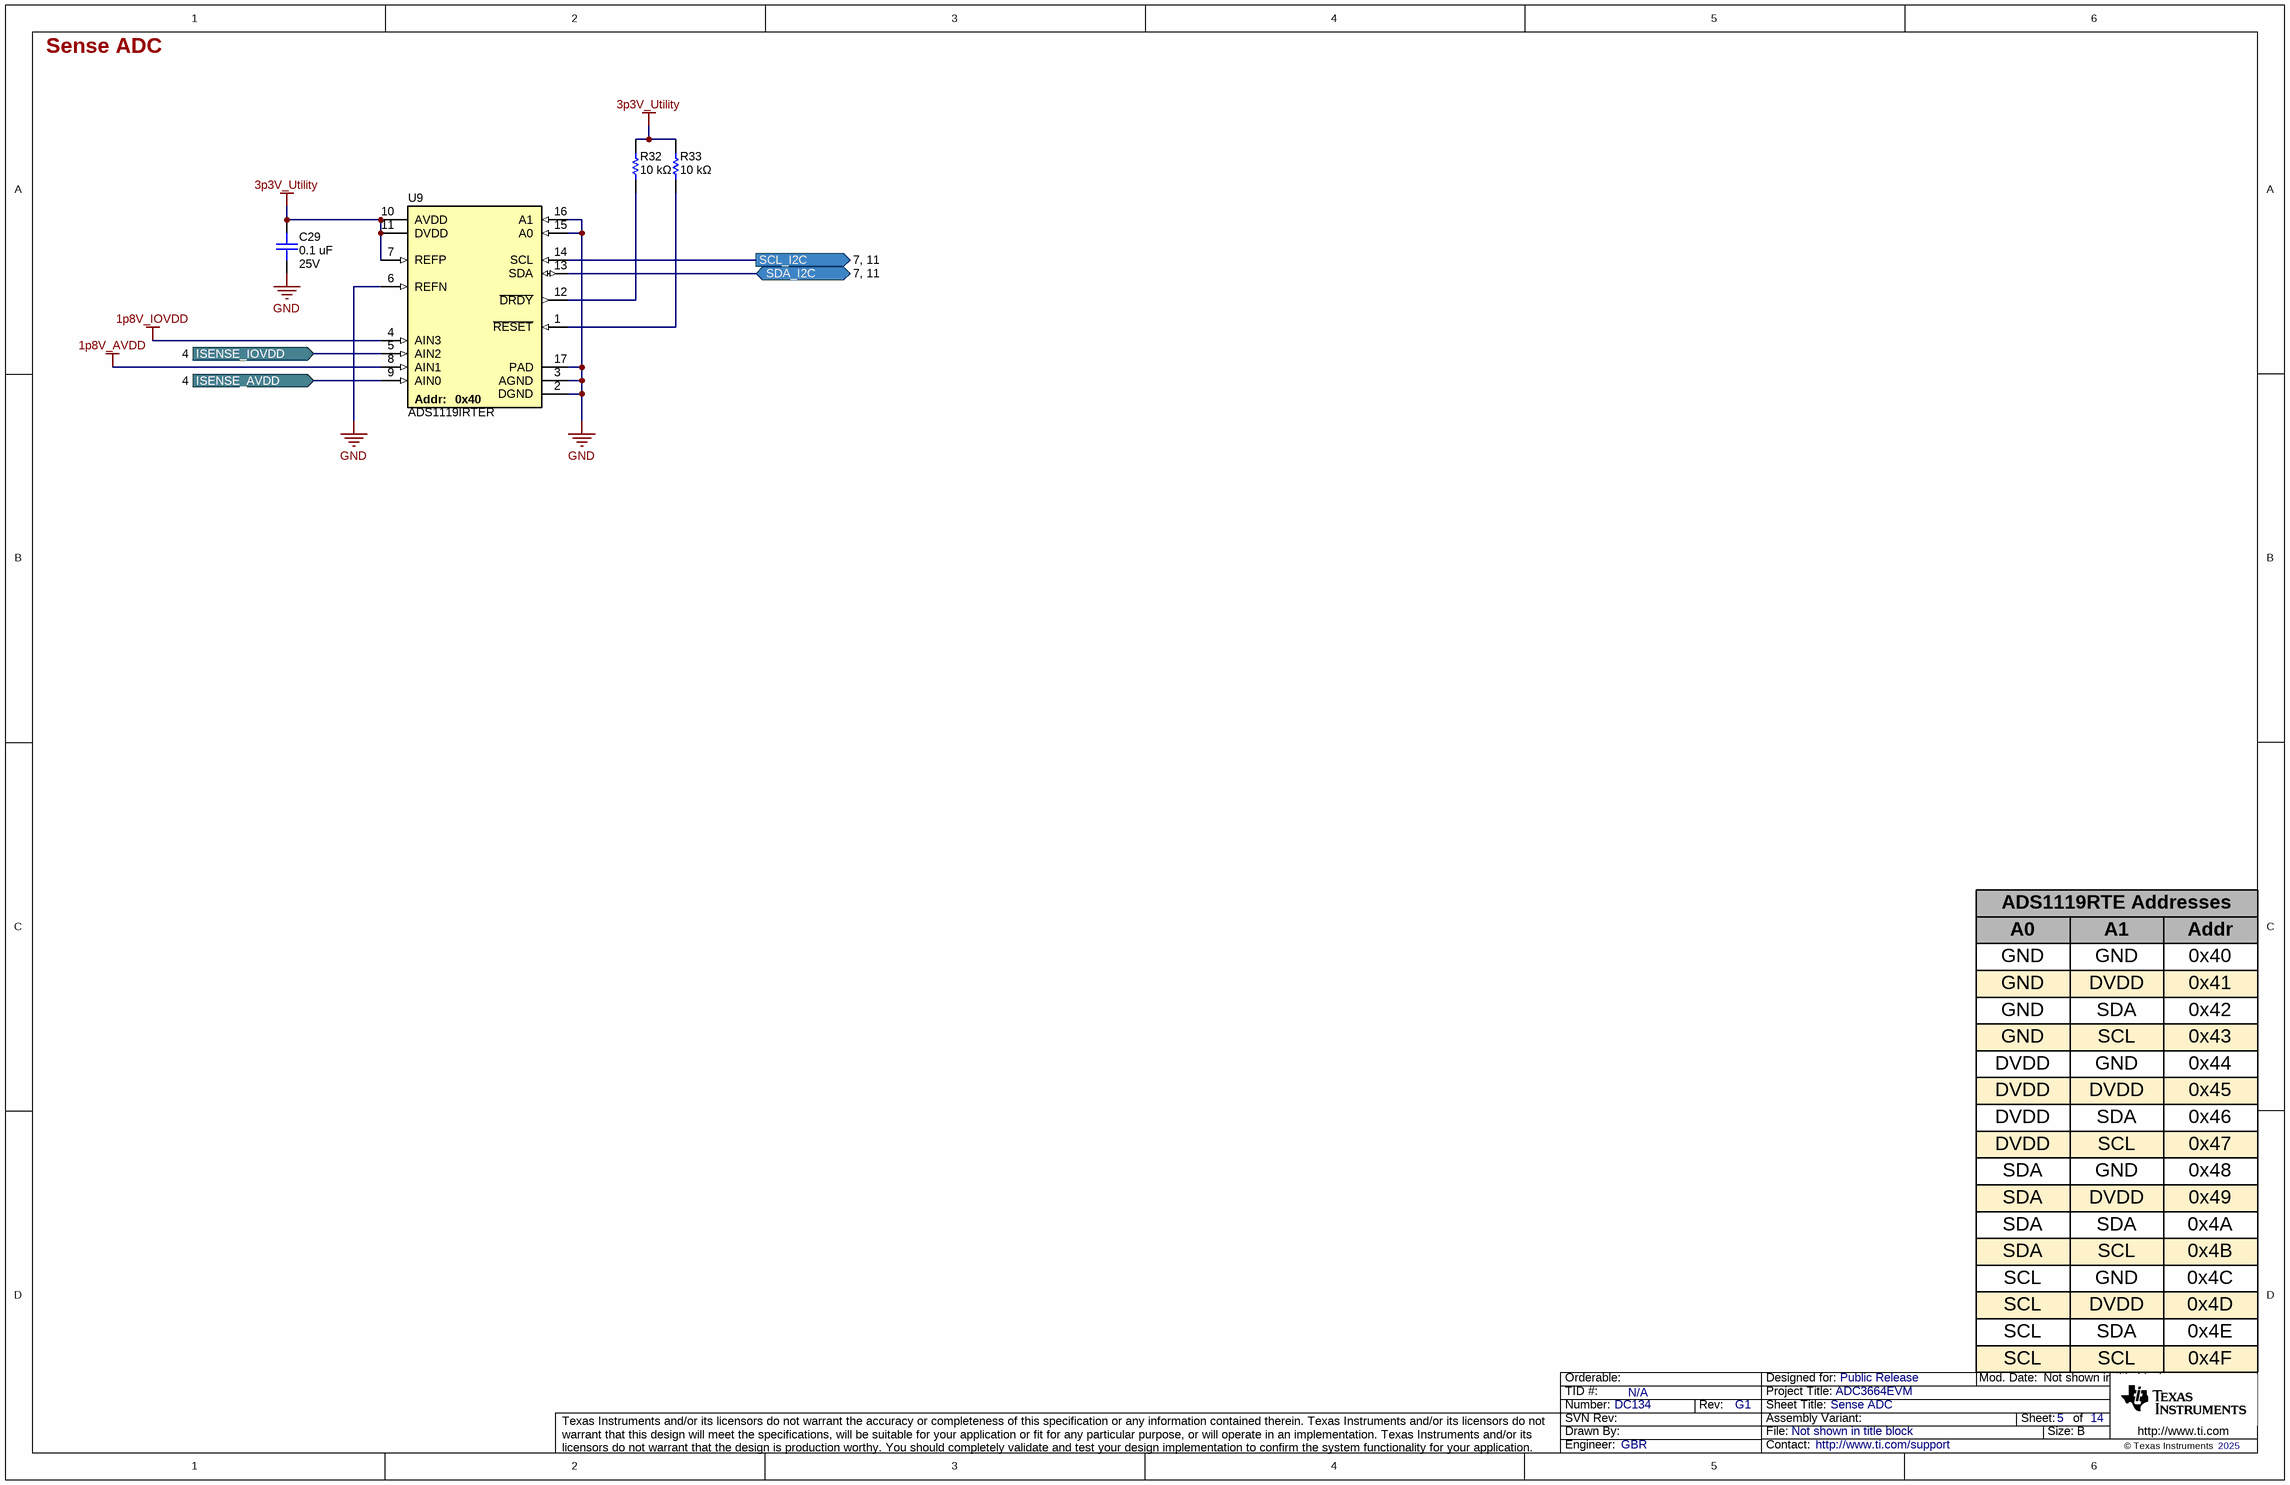
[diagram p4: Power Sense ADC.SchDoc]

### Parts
C29  value 0.1 uF  Voltage - Rated: 25V  [0402L_cap]  (hidden comment: GRT155R71E104KE01J)
R32  value 10 kΩ  [0402L]  (hidden comment: ERA-2AEB103X)
R33  value 10 kΩ  [0402L]  (hidden comment: ERA-2AEB103X)
U9  ADS1119IRTER  Addresss: 0x40  [RTE0016D]

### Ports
ISENSE_AVDD (in, see 4), ISENSE_IOVDD (in, see 4), SCL_I2C (out, see 7, 11), SDA_I2C (bidir, see 7, 11)

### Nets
1p8V_AVDD: U9.8(AIN1)
1p8V_IOVDD: U9.4(AIN3)
3p3V_Utility: C29.2 R32.2 R33.2 U9.7(REFP) U9.10(AVDD) U9.11(DVDD)
GND: C29.1 U9.2(DGND) U9.3(AGND) U9.6(REFN) U9.15(A0) U9.16(A1) U9.17(PAD)
ISENSE_AVDD: U9.9(AIN0) ; port ISENSE_AVDD
ISENSE_IOVDD: U9.5(AIN2) ; port ISENSE_IOVDD
SCL_I2C: U9.14(SCL) ; port SCL_I2C
SDA_I2C: U9.13(SDA) ; port SDA_I2C
NetR32_1: R32.1 U9.12(~{DRDY})
NetR33_1: R33.1 U9.1(~{RESET})

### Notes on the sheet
- A0
- GND
- ADS1119RTE Addresses
- A1
- Addr
- 0x40
- DVDD
- SDA
- 0x41
- 0x42
- SCL
- 0x43
- 0x44
- 0x45
- 0x46
- 0x47
- 0x48
- 0x49
- 0x4A
- 0x4B
- 0x4C
- 0x4D
- 0x4E
- 0x4F

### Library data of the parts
C29 = capcc09401: as C17 on sheet Power LDO
R32 R33 = RSMD040200315: as R5 on sheet 12V Input, Efuse and 3p3V Utility
U9 = ADS1119IRTER: 16-Bit, 4-Channel, 1-kSPS, Delta-Sigma ADC with I2C Interface, RTE0016D (WQFN-16); Alternate PartNumber: ADS1119IRTET; Alternate Manufacturer: Texas Instruments; SizeAreaWB_mm2: 16; SizeZ_mm: 0.8; SizeX_mm: 3; SizeArea_mm2: 9; AEC Qualified: N; AEC Category: Q200

## Sheet USB Control FTDI.SchDoc: FTDI Control
size 431 x 279 mm; Date: Not shown in title block; ApprovedBy: Not shown in title block; CheckedBy: Not shown in title block; Author: Not shown in title block; CompanyName: Not shown in title block; Engineer: Not shown in title block; Organization: Not shown in title block; Address1: Not shown in title block; Address2: Not shown in title block; Address3: Not shown in title block; Address4: Not shown in title block; DocumentNumber: 1; Revision: Use project parameter SCH_Rev; SheetNumber: 6; SheetTotal: 14; PageSetup: Record=PageOptions¦CenterHorizontal=True¦CenterVertical=True¦PrintScale=1.00¦XCorrection=1.00¦YCorrection=1.00¦PrintKind=0¦BorderSize=5000000¦LeftOffset=0¦BottomOffset=0¦Orientation=2¦PaperLength=1000¦PaperWidth=1000¦Scale=100¦PaperSource=15¦PrintQuality=600¦MediaType=1¦DitherType=10¦PaperKind=Letter¦PrintScaleMode=1
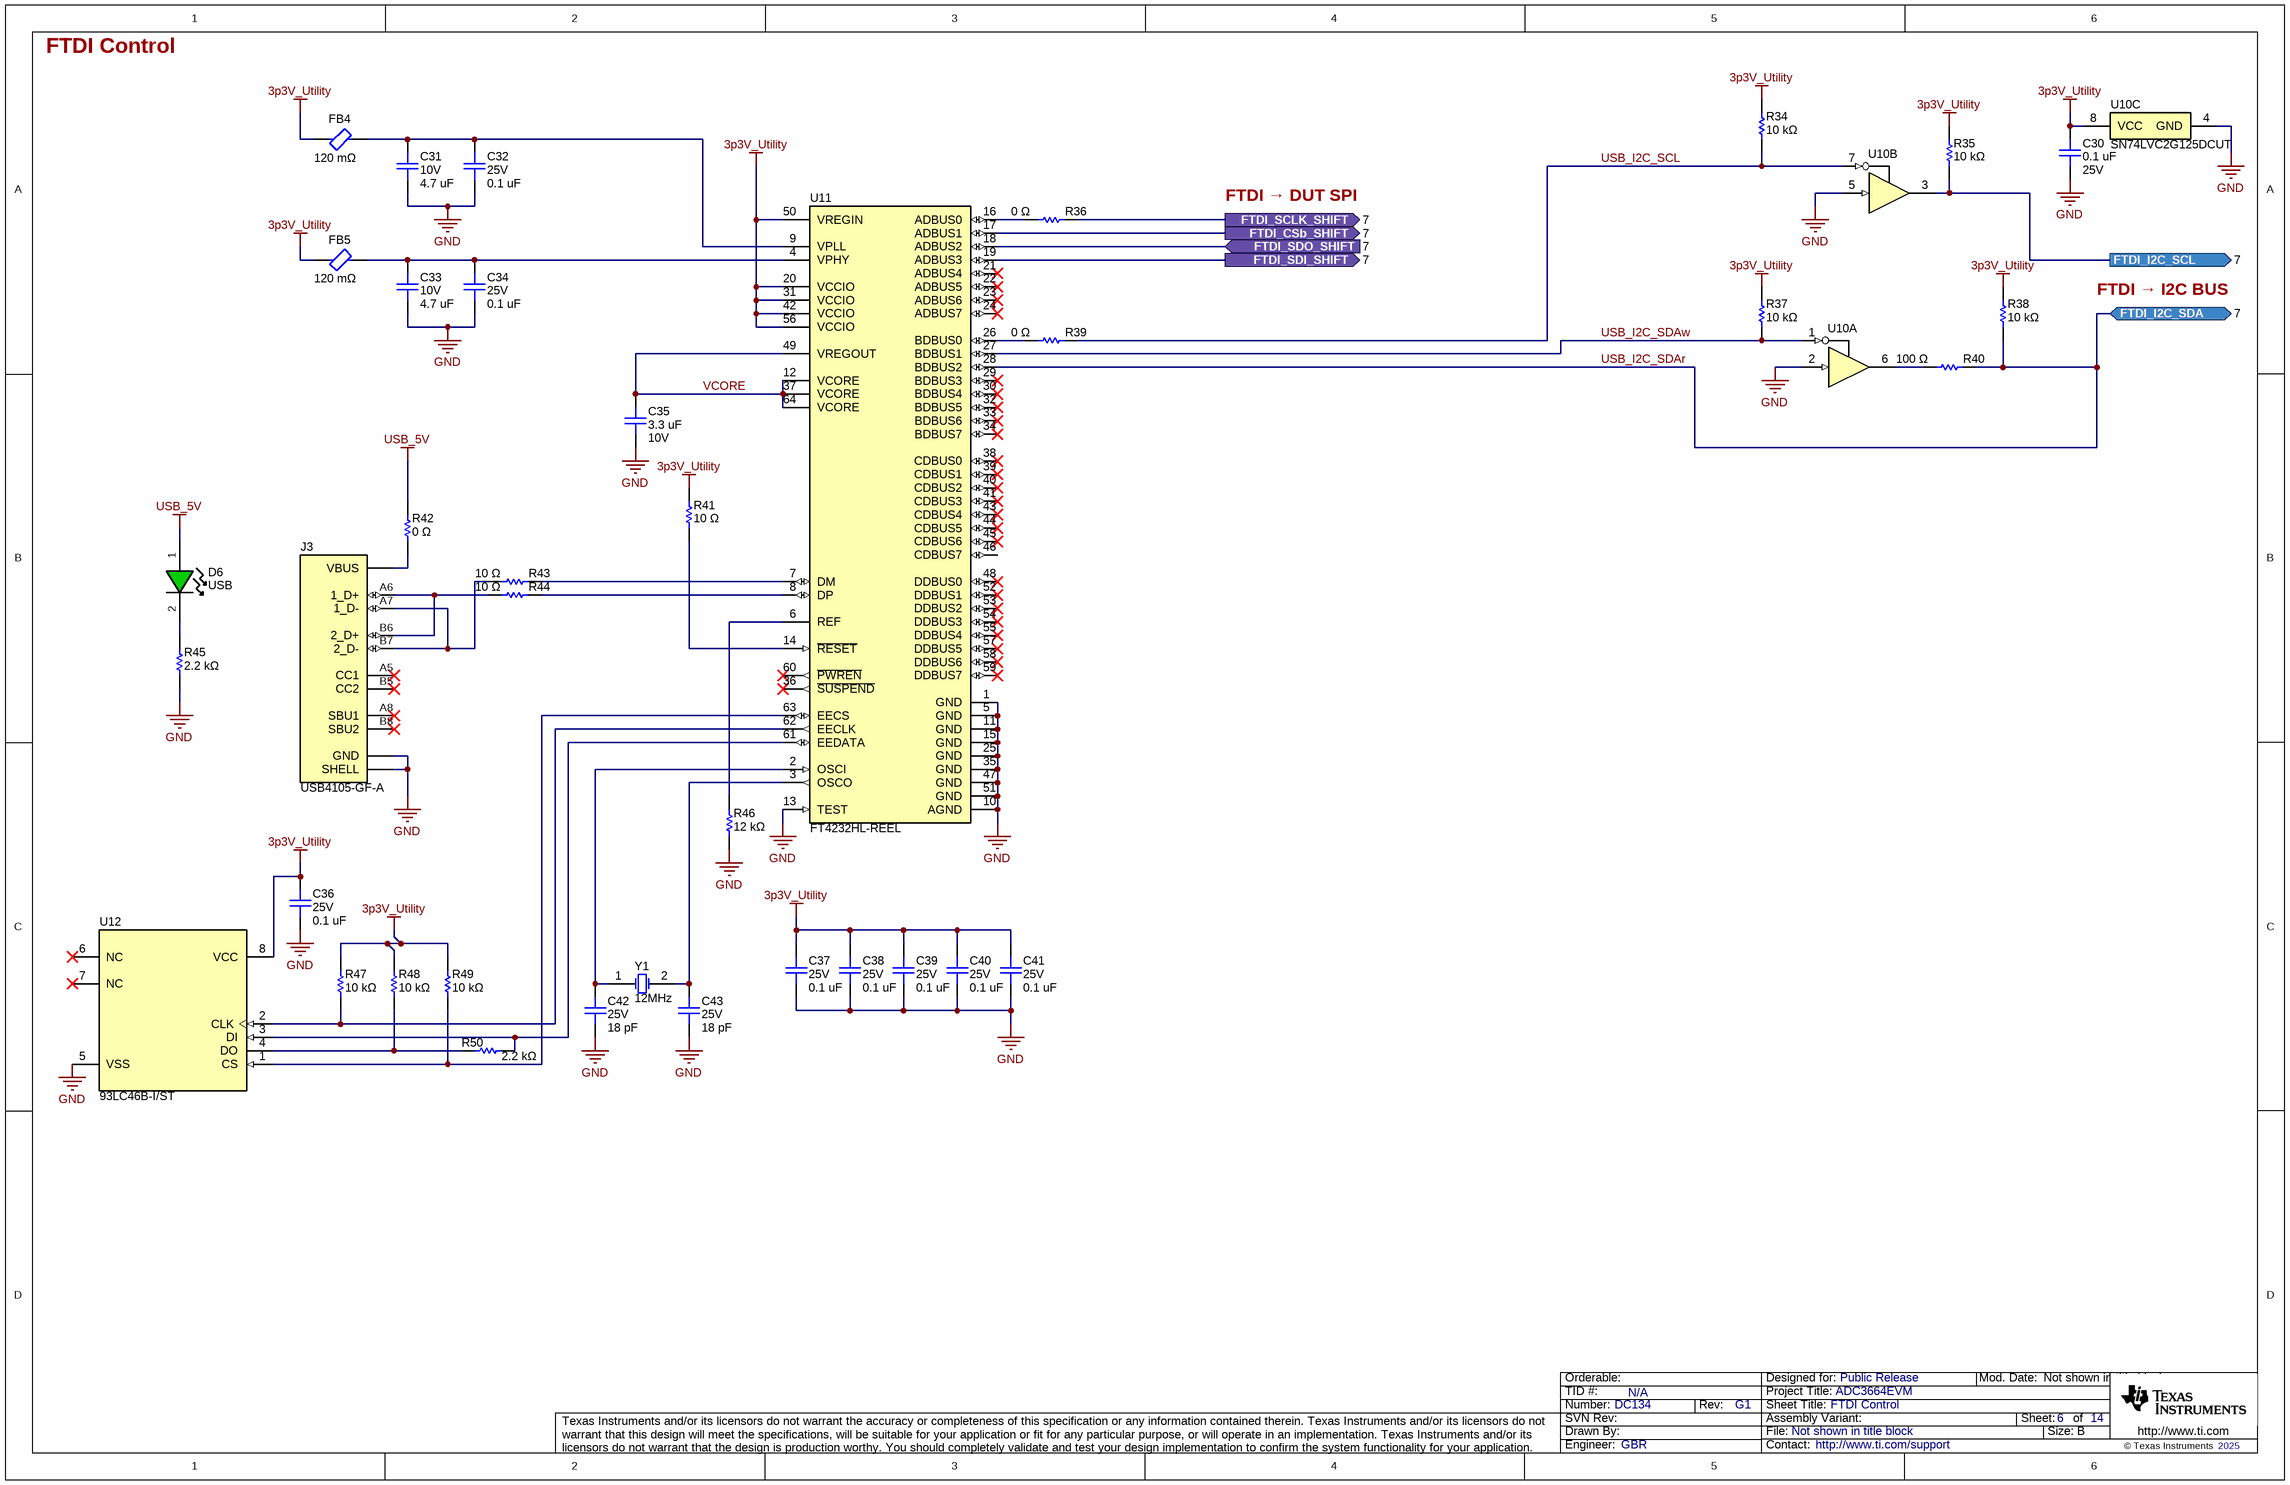
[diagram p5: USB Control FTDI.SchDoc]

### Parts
C30  value 0.1 uF  Voltage - Rated: 25V  [0402L_cap]  (hidden comment: GRT155R71E104KE01J)
C31  value 4.7 uF  Voltage - Rated: 10V  [0402L_cap]  (hidden comment: C1005X5R1A475K050BC)
C32  value 0.1 uF  Voltage - Rated: 25V  [0402L_cap]  (hidden comment: GRT155R71E104KE01J)
C33  value 4.7 uF  Voltage - Rated: 10V  [0402L_cap]  (hidden comment: C1005X5R1A475K050BC)
C34  value 0.1 uF  Voltage - Rated: 25V  [0402L_cap]  (hidden comment: GRT155R71E104KE01J)
C35  value 3.3 uF  Voltage - Rated: 10V  [0603L_cap]  (hidden comment: CGA3E1X5R1A335K080AC)
C36  value 0.1 uF  Voltage - Rated: 25V  [0402L_cap]  (hidden comment: GRT155R71E104KE01J)
C37  value 0.1 uF  Voltage - Rated: 25V  [0402L_cap]  (hidden comment: GRT155R71E104KE01J)
C38  value 0.1 uF  Voltage - Rated: 25V  [0402L_cap]  (hidden comment: GRT155R71E104KE01J)
C39  value 0.1 uF  Voltage - Rated: 25V  [0402L_cap]  (hidden comment: GRT155R71E104KE01J)
C40  value 0.1 uF  Voltage - Rated: 25V  [0402L_cap]  (hidden comment: GRT155R71E104KE01J)
C41  value 0.1 uF  Voltage - Rated: 25V  [0402L_cap]  (hidden comment: GRT155R71E104KE01J)
C42  value 18 pF  Voltage - Rated: 25V  [0201_cap]  (hidden comment: GJM0336C1E180JB01J)
C43  value 18 pF  Voltage - Rated: 25V  [0201_cap]  (hidden comment: GJM0336C1E180JB01J)
D6  Text1: USB  [LED_LTST-C190-Green]  (hidden comment: LTST-C191TGKT)
FB4  DCR: 120 mΩ  [0402L]  (hidden comment: NFZ15SG151SN11D)
FB5  DCR: 120 mΩ  [0402L]  (hidden comment: NFZ15SG151SN11D)
J3  USB4105-GF-A  [FP-USB4105-GF-A_CONN_USB_9MM58_7MM53-MFG]
R34  value 10 kΩ  [0402L]  (hidden comment: ERA-2AEB103X)
R35  value 10 kΩ  [0402L]  (hidden comment: ERA-2AEB103X)
R36  value 0 Ω  [0201]  (hidden comment: ERJ-1GN0R00C)
R37  value 10 kΩ  [0402L]  (hidden comment: ERA-2AEB103X)
R38  value 10 kΩ  [0402L]  (hidden comment: ERA-2AEB103X)
R39  value 0 Ω  [0201]  (hidden comment: ERJ-1GN0R00C)
R40  value 100 Ω  [0402L]  (hidden comment: ERJ-2RKF1000X)
R41  value 10 Ω  [0402L]  (hidden comment: ERJ-2GEJ100X)
R42  value 0 Ω  [0805L]  (hidden comment: ERJ-6GEY0R00V)
R43  value 10 Ω  [0402L]  (hidden comment: ERJ-2GEJ100X)
R44  value 10 Ω  [0402L]  (hidden comment: ERJ-2GEJ100X)
R45  value 2.2 kΩ  [0402L]  (hidden comment: ERJ-2GEJ222X)
R46  value 12 kΩ  [0402L]  (hidden comment: ERJ-2RKF1202X)
R47  value 10 kΩ  [0402L]  (hidden comment: ERA-2AEB103X)
R48  value 10 kΩ  [0402L]  (hidden comment: ERA-2AEB103X)
R49  value 10 kΩ  [0402L]  (hidden comment: ERA-2AEB103X)
R50  value 2.2 kΩ  [0402L]  (hidden comment: ERJ-2GEJ222X)
U10  SN74LVC2G125DCUT  [DCU0008A]  (value not drawn)  (parts A,B,C of 3)
U11  FT4232HL-REEL  [LQFP64-MFG]
U12  93LC46B-I/ST  [TSSOP-8]
Y1  Text1: 12MHz  [XTAL_ABM3]  (hidden comment: ABM3-12.000MHZ-D2Y-T)

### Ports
FTDI_CSb_SHIFT (out, see 7), FTDI_I2C_SCL (out, see 7), FTDI_I2C_SDA (bidir, see 7), FTDI_SCLK_SHIFT (out, see 7), FTDI_SDI_SHIFT (out, see 7), FTDI_SDO_SHIFT (in, see 7)

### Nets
3p3V_Utility: C30.2 C36.2 C37.2 C38.2 C39.2 C40.2 C41.2 FB4.1 FB5.1 R34.2 R35.1 R37.2 R38.1 R41.2 R47.2 R48.2 R49.2 U10.8(VCC) U11.20(VCCIO) U11.31(VCCIO) U11.42(VCCIO) U11.50(VREGIN) U11.56(VCCIO) U12.8(VCC)
GND: C30.1 C31.1 C32.1 C33.1 C34.1 C35.1 C36.1 C37.1 C38.1 C39.1 C40.1 C41.1 C42.1 C43.1 J3.1,2,3,4(SHELL) J3.A1,B1(GND) R45.1 R46.1 U10.2(1A) U10.4(GND) U10.5(2A) U11.1(GND) U11.5(GND) U11.10(AGND) U11.11(GND) U11.13(TEST) U11.15(GND) U11.25(GND) U11.35(GND) U11.47(GND) U11.51(GND) U12.5(VSS)
USB_5V: D6.1(A) R42.2
FTDI_CSb_SHIFT: U11.17(ADBUS1) ; port FTDI_CSb_SHIFT
FTDI_I2C_SCL: R35.2 U10.3(2Y) ; port FTDI_I2C_SCL
FTDI_SCLK_SHIFT: R36.2 ; port FTDI_SCLK_SHIFT
FTDI_SDI_SHIFT: U11.19(ADBUS3) ; port FTDI_SDI_SHIFT
FTDI_SDO_SHIFT: U11.18(ADBUS2) ; port FTDI_SDO_SHIFT
USB_I2C_SCL: R34.1 R39.2 U10.7(2~{OE})
USB_I2C_SDAr: R38.2 R40.2 U11.28(BDBUS2) ; port FTDI_I2C_SDA
USB_I2C_SDAw: R37.1 U10.1(1~{OE}) U11.27(BDBUS1)
VCORE: C35.2 U11.12(VCORE) U11.37(VCORE) U11.49(VREGOUT) U11.64(VCORE)
NetC31_2: C31.2 C32.2 FB4.2 U11.9(VPLL)
NetC33_2: C33.2 C34.2 FB5.2 U11.4(VPHY)
NetC42_2: C42.2 U11.2(OSCI) Y1.1(OSC1)
NetC43_2: C43.2 U11.3(OSCO) Y1.2(OSC2)
NetD6_2: D6.2(K) R45.2
NetJ3_A4,B4: J3.A4,B4(VBUS) R42.1
NetJ3_A6: J3.A6(1_D+) J3.B6(2_D+) R44.1
NetJ3_A7: J3.A7(1_D-) J3.B7(2_D-) R43.1
NetR36_1: R36.1 U11.16(ADBUS0)
NetR39_1: R39.1 U11.26(BDBUS0)
NetR40_1: R40.1 U10.6(1Y)
NetR41_1: R41.1 U11.14(~{RESET})
NetR43_2: R43.2 U11.7(DM)
NetR44_2: R44.2 U11.8(DP)
NetR46_2: R46.2 U11.6(REF)
NetR47_1: R47.1 U11.62(EECLK) U12.2(CLK)
NetR48_1: R48.1 R50.1 U12.4(DO)
NetR49_1: R49.1 U11.63(EECS) U12.1(CS)
NetR50_2: R50.2 U11.61(EEDATA) U12.3(DI)

Not connected (* = marked no-connect by the designer): J3 A5(CC1)* A8(SBU1)* B5(CC2)* B8(SBU2)*; U11 21(ADBUS4)* 22(ADBUS5)* 23(ADBUS6)* 24(ADBUS7)* 29(BDBUS3)* 30(BDBUS4)* 32(BDBUS5)* 33(BDBUS6)* 34(BDBUS7)* 36(~{SUSPEND})* 38(CDBUS0)* 39(CDBUS1)* 40(CDBUS2)* 41(CDBUS3)* 43(CDBUS4)* 44(CDBUS5)* 45(CDBUS6)* 46(CDBUS7) 48(DDBUS0)* 52(DDBUS1)* 53(DDBUS2)* 54(DDBUS3)* 55(DDBUS4)* 57(DDBUS5)* 58(DDBUS6)* 59(DDBUS7)* 60(~{PWREN})*; U12 6(NC)* 7(NC)*

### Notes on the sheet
- FTDI → DUT SPI
- FTDI → I2C BUS

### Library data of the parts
C30 C32 C34 C36-C41 = capcc09401: as C17 on sheet Power LDO
C31 C33 = capcc03298: CAP CER 4.7UF 10V X5R 0402; Manufacturer: TDK Corporation; CompType: Capacitor Ceramic; Tolerance: ±10%; SizeX_mm: 1; SizeY_mm: 0.5; SizeZ_mm: 0.65
C35 = capcc03130: CAP CER 3.3UF 10V X5R 0603; Manufacturer: TDK Corporation; CompType: Capacitor Ceramic; Tolerance: ±10%; SizeX_mm: 1.6; SizeY_mm: 0.8; SizeZ_mm: 0.9
C42 C43 = capcc08580: CAP CER 18PF 25V C0H 0201; Manufacturer: Murata Electronics; CompType: Capacitor Ceramic; Tolerance: ±5%; SizeX_mm: 0.6; SizeY_mm: 0.3; SizeZ_mm: 0.33
D6 = cmp00247: as D1 on sheet 12V Input, Efuse and 3p3V Utility
FB4 FB5 = dcp00209: 0402 (1005) 150OHM (TYP.) 1000MA; Manufacturer: Murata Electronics; Current: 1A
J3 = USB4105-GF-A: USB - C (Type - C) USB 2.0 Receptacle Connector 24 Position Surface Mount, Right Angle; Through Hole; Manufacturer: GCT; CompType: USB C
R34 R35 R37 R38 R47-R49 = RSMD040200315: as R5 on sheet 12V Input, Efuse and 3p3V Utility
R36 R39 = RSMD020101699: RES SMD 0 OHM JUMPER 1/20W 0201; Manufacturer: Panasonic Electronic Components; CompType: Resistor SMD; Power (Watts): 0.05W, 1/20W
R40 = RSMD040200375: RES SMD 100 OHM 1% 1/10W 0402; Manufacturer: Panasonic Electronic Components; CompType: Resistor SMD; Power (Watts): 0.1W, 1/10W; Temperature Coefficient: ±100ppm/°C; SizeX_mm: 1; SizeY_mm: 0.5; SizeZ_mm: 0.4
R41 R43 R44 = RSMD040200327: RES SMD 10 OHM 5% 1/10W 0402; Manufacturer: Panasonic Electronic Components; CompType: Resistor SMD; Power (Watts): 0.1W, 1/10W; Temperature Coefficient: ±200ppm/°C; SizeX_mm: 1; SizeY_mm: 0.5; SizeZ_mm: 0.4
R42 = RSMD080510615: RES SMD 0 OHM JUMPER 1/8W 0805; Manufacturer: Panasonic Electronic Components; CompType: Resistor SMD; Power (Watts): 0.125W, 1/8W; SizeX_mm: 2; SizeY_mm: 1.25; SizeZ_mm: 0.7
R45 R50 = RSMD040201206: RES SMD 2.2K OHM 5% 1/10W 0402; Manufacturer: Panasonic Electronic Components; CompType: Resistor SMD; Power (Watts): 0.1W, 1/10W; Temperature Coefficient: ±200ppm/°C; SizeX_mm: 1; SizeY_mm: 0.5; SizeZ_mm: 0.4
R46 = RSMD040200519: as R8 on sheet 12V Input, Efuse and 3p3V Utility
U10 = SN74LVC2G125DCUT: Dual Bus Buffer Gate with 3-State Outputs, DCU0008A (VSSOP-8); Manufacturer: Texas Instruments; F @ Nom Voltage(Max)(Mhz): 150; VCC(Min)(V): 1.65; Bits(#): 2; Output Type: CMOS; Technology Family: LVC; Rating: Catalog; tpd @ Nom Voltage(Max)(ns): 9.1,4.8,4.3,3.7; 3-State Output: Yes; Schmitt Trigger: No; Logic: True; Voltage(Nom)(V): 1.8,2.5,3.3,5; Output Drive (IOL/IOH)(Max)(mA): 32/-32; ICC @ Nom Voltage(Max)(mA): 0.01; Input Type: CMOS/TTL; VCC(Max)(V): 5.5; AEC Category: Q200; AEC Qualified: N; CompType: IC; SizeAreaWB_mm2: 12.6; SizeArea_mm2: 6.4; SizeX_mm: 3.2; SizeY_mm: 2.0; SizeZ_mm: 0.9
U11 = cmp00204: USB Interface IC USB HS to Quad UART/ SPI/JTAG/I2C LQFP-6; Manufacturer: FTDI; Alt PartNumber: FT4232HL-TRAY; Symbol Name: SYM-FT4232HL-REEL; CompType: uC
U12 = cmp00156: 1K Microwire Compatible Serial EEPROM; Manufacturer: Microchip Technology; SymbolCreator: Altium; SizeArea_mm2: 19.2; SizeAreaWB_mm2: 42
Y1 = cmp00323: 12 MHz ±20ppm Crystal 18pF 60 Ohms 2-SMD, No Lead; Manufacturer: Abracon LLC; CompType: XO

## Sheet Comms LVL Shift and MUX.SchDoc: Comms Lvl Shift & Mux
size 431 x 279 mm; Date: Not shown in title block; ApprovedBy: Not shown in title block; CheckedBy: Not shown in title block; Author: Not shown in title block; CompanyName: Not shown in title block; Engineer: Not shown in title block; Organization: Not shown in title block; Address1: Not shown in title block; Address2: Not shown in title block; Address3: Not shown in title block; Address4: Not shown in title block; DocumentNumber: 1; Revision: Use project parameter SCH_Rev; SheetNumber: 7; SheetTotal: 14; PageSetup: Record=PageOptions¦CenterHorizontal=True¦CenterVertical=True¦PrintScale=1.00¦XCorrection=1.00¦YCorrection=1.00¦PrintKind=0¦BorderSize=5000000¦LeftOffset=0¦BottomOffset=0¦Orientation=2¦PaperLength=1000¦PaperWidth=1000¦Scale=100¦PaperSource=15¦PrintQuality=600¦MediaType=1¦DitherType=10¦PaperKind=Letter¦PrintScaleMode=1
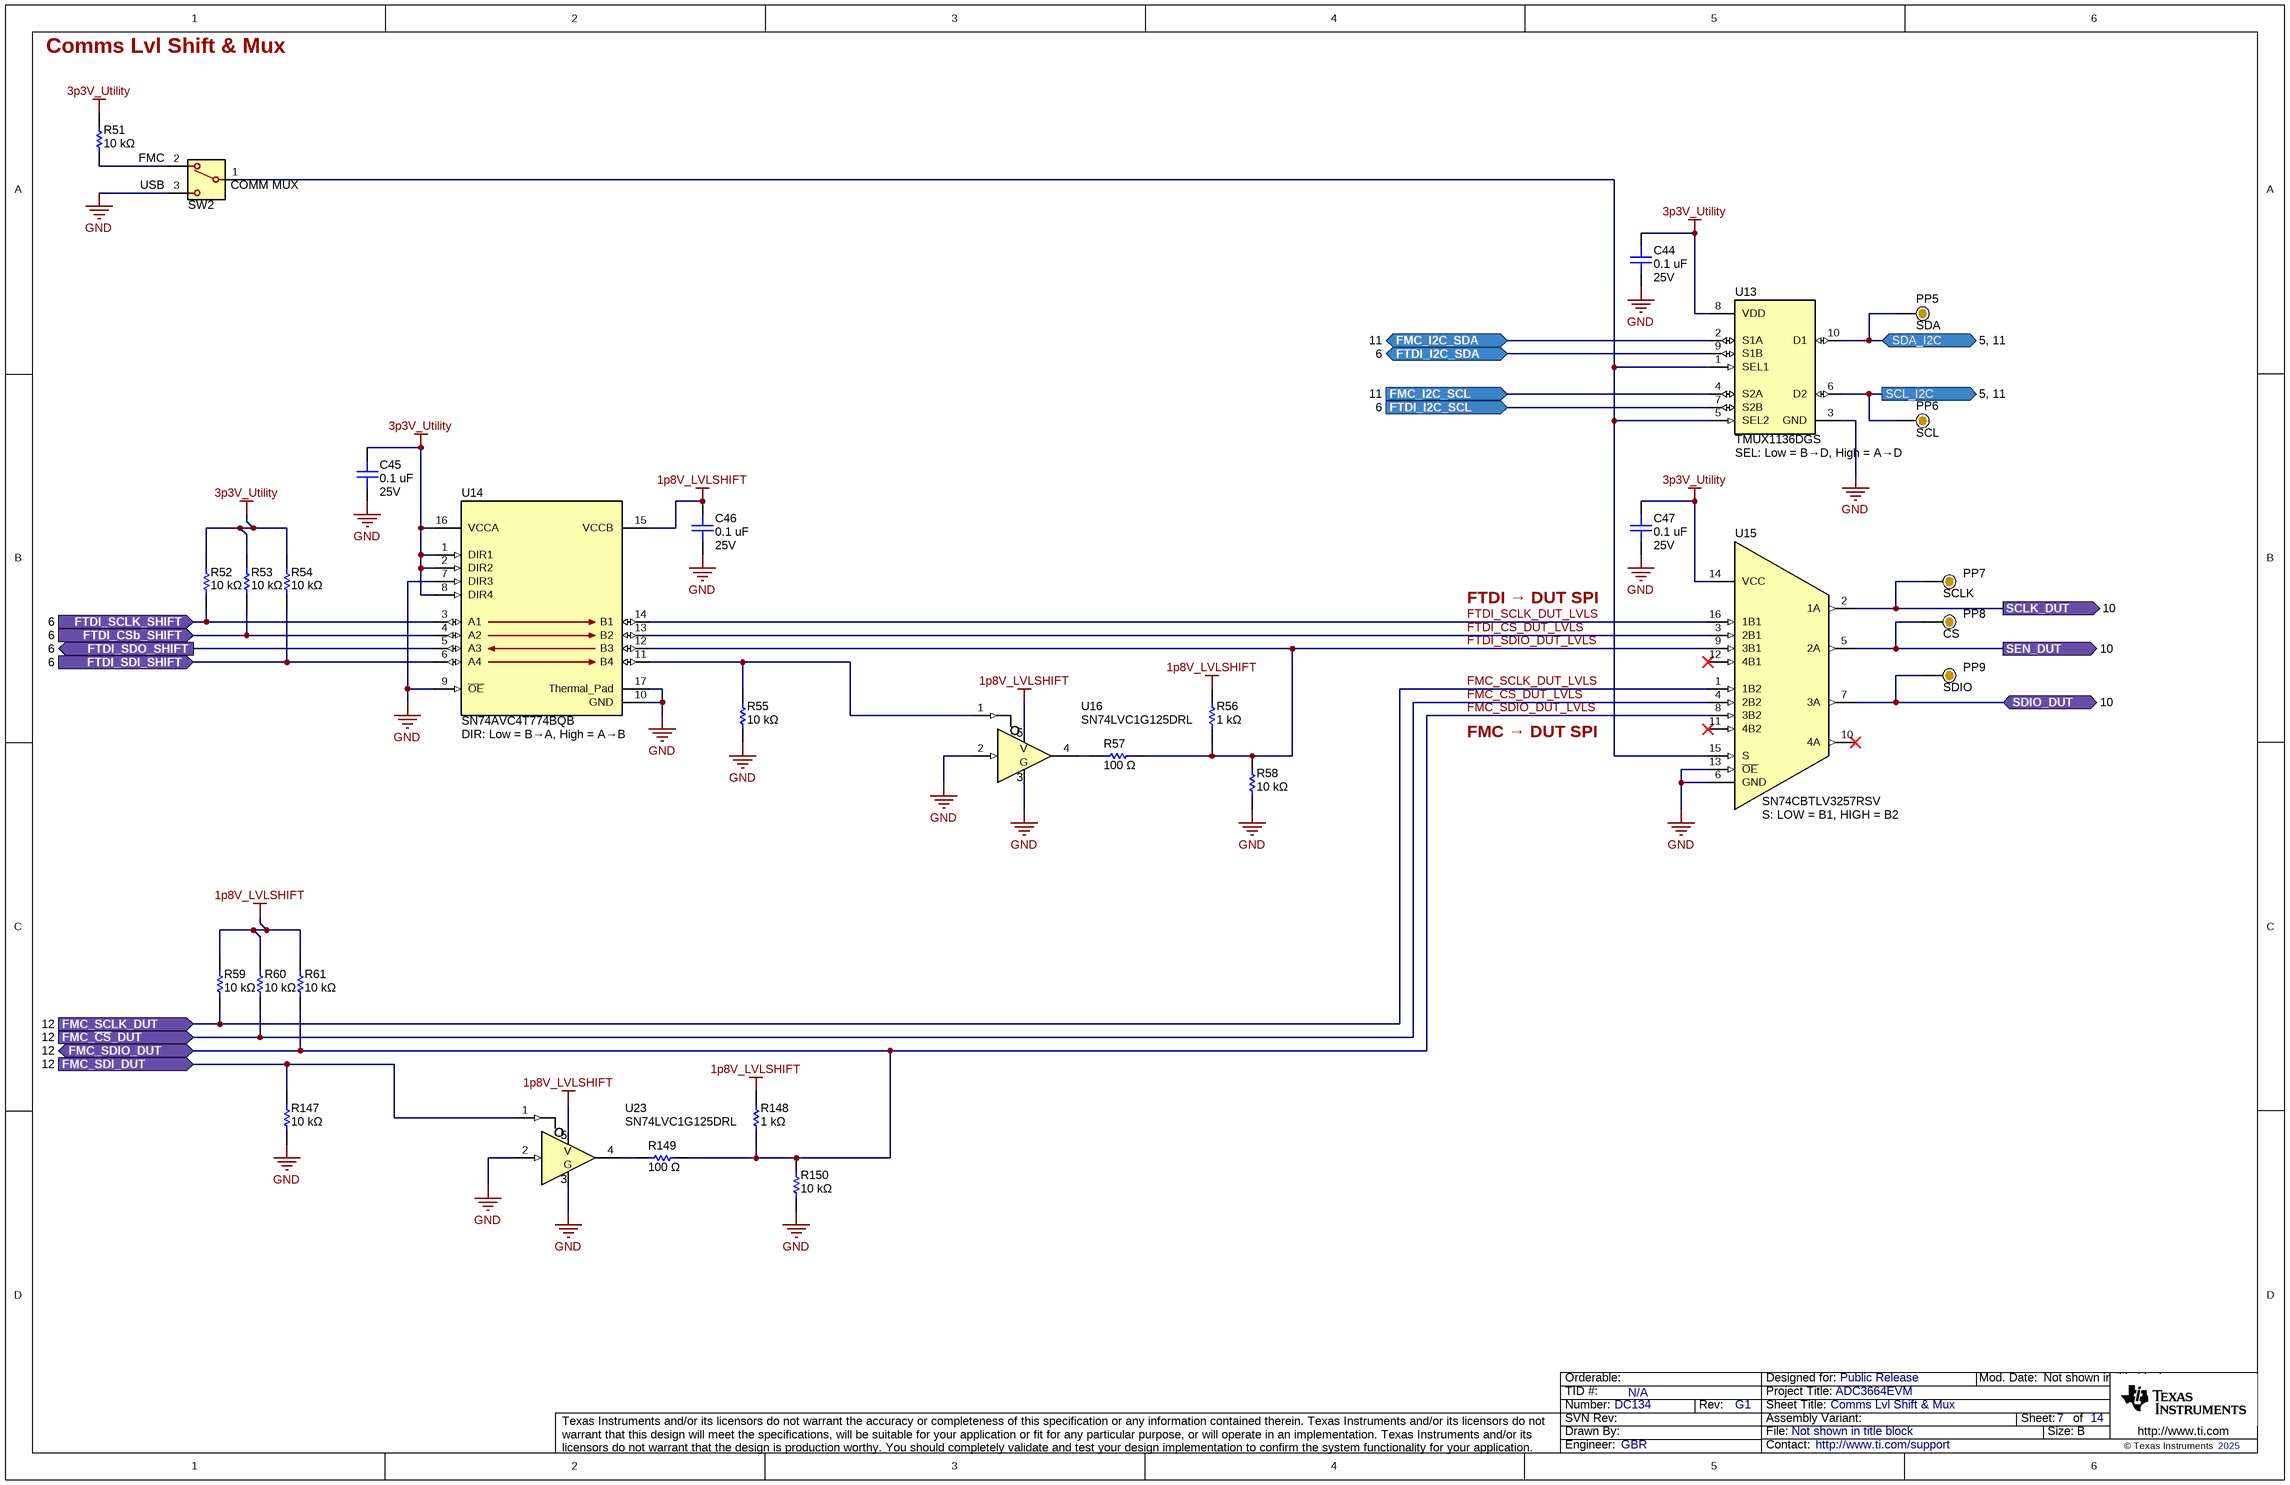
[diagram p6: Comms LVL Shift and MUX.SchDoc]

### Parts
C44  value 0.1 uF  Voltage - Rated: 25V  [0402L_cap]  (hidden comment: GRT155R71E104KE01J)
C45  value 0.1 uF  Voltage - Rated: 25V  [0402L_cap]  (hidden comment: GRT155R71E104KE01J)
C46  value 0.1 uF  Voltage - Rated: 25V  [0402L_cap]  (hidden comment: GRT155R71E104KE01J)
C47  value 0.1 uF  Voltage - Rated: 25V  [0402L_cap]  (hidden comment: GRT155R71E104KE01J)
PP5  Text1: SDA  [ProbePoint_TH_40mil]  (hidden comment: Probe Point)  (no BOM)
PP6  Text1: SCL  [ProbePoint_TH_40mil]  (hidden comment: Probe Point)  (no BOM)
PP7  Text1: SCLK  [ProbePoint_TH_40mil]  (hidden comment: Probe Point)  (no BOM)
PP8  Text1: CS  [ProbePoint_TH_40mil]  (hidden comment: Probe Point)  (no BOM)
PP9  Text1: SDIO  [ProbePoint_TH_40mil]  (hidden comment: Probe Point)  (no BOM)
R51  value 10 kΩ  [0402L]  (hidden comment: ERA-2AEB103X)
R52  value 10 kΩ  [0402L]  (hidden comment: ERA-2AEB103X)
R53  value 10 kΩ  [0402L]  (hidden comment: ERA-2AEB103X)
R54  value 10 kΩ  [0402L]  (hidden comment: ERA-2AEB103X)
R55  value 10 kΩ  [0402L]  (hidden comment: ERA-2AEB103X)
R56  value 1 kΩ  [0402L]  (hidden comment: ERJ-U02J102X)
R57  value 100 Ω  [0402L]  (hidden comment: ERJ-2RKF1000X)
R58  value 10 kΩ  [0402L]  (hidden comment: ERA-2AEB103X)
R59  value 10 kΩ  [0402L]  (hidden comment: ERA-2AEB103X)
R60  value 10 kΩ  [0402L]  (hidden comment: ERA-2AEB103X)
R61  value 10 kΩ  [0402L]  (hidden comment: ERA-2AEB103X)
R147  value 10 kΩ  [0402L]  (hidden comment: ERA-2AEB103X)
R148  value 1 kΩ  [0402L]  (hidden comment: ERJ-U02J102X)
R149  value 100 Ω  [0402L]  (hidden comment: ERJ-2RKF1000X)
R150  value 10 kΩ  [0402L]  (hidden comment: ERA-2AEB103X)
SW2  Text1: COMM MUX  Text2: FMC  Text3: USB  [450301014042]  (hidden comment: cmp00353)
U13  TMUX1136DGS  Text1: SEL: Low = B→D, High = A→D  [DQA0010A]
U14  SN74AVC4T774BQB  Text1: DIR: Low = B→A, High = A→B  [BQB0016A-MFG]
U15  SN74CBTLV3257RSV  Text1: S: LOW = B1, HIGH = B2  [RSV0016A]
U16  SN74LVC1G125DRL  [DRL0005A]
U23  SN74LVC1G125DRL  [DRL0005A]

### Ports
FMC_I2C_SCL (in, see 11), FMC_I2C_SDA (bidir, see 11), FMC_SCLK_DUT (in, see 12), FMC_SDI_DUT (in, see 12), FMC_SDIO_DUT (bidir, see 12), FMC_~{CS}_DUT (in, see 12), FTDI_CSb_SHIFT (in, see 6), FTDI_I2C_SCL (in, see 6), FTDI_I2C_SDA (bidir, see 6), FTDI_SCLK_SHIFT (in, see 6), FTDI_SDI_SHIFT (in, see 6), FTDI_SDO_SHIFT (out, see 6), SCL_I2C (out, see 5, 11), SCLK_DUT (out, see 10), SDA_I2C (bidir, see 5, 11), SDIO_DUT (bidir, see 10), SEN_DUT (out, see 10)

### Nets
1p8V_LVLSHIFT: C46.2 R56.1 R59.2 R60.2 R61.2 R148.1 U14.15(VCCB) U16.5(VCC) U23.5(VCC)
3p3V_Utility: C44.2 C45.2 C47.2 R51.2 R52.2 R53.2 R54.2 U13.8(VDD) U14.1(DIR1) U14.2(DIR2) U14.8(DIR4) U14.16(VCCA) U15.14(VCC)
GND: C44.1 C45.1 C46.1 C47.1 R55.1 R58.2 R147.1 R150.2 SW2.3 U13.3(GND) U14.7(DIR3) U14.9(~{OE}) U14.10(GND) U14.17(Thermal_Pad) U15.6(GND) U15.13(~{OE}) U16.2(A) U16.3(GND) U23.2(A) U23.3(GND)
FMC_~{CS}_DUT_LVLS: R60.1 U15.4(2B2) ; port FMC_~{CS}_DUT
FMC_I2C_SCL: U13.4(S2A) ; port FMC_I2C_SCL
FMC_I2C_SDA: U13.2(S1A) ; port FMC_I2C_SDA
FMC_SCLK_DUT_LVLS: R59.1 U15.1(1B2) ; port FMC_SCLK_DUT
FMC_SDI_DUT: R147.2 U23.1(~{OE}) ; port FMC_SDI_DUT
FMC_SDIO_DUT_LVLS: R61.1 R148.2 R149.2 R150.1 U15.8(3B2) ; port FMC_SDIO_DUT
FTDI_~{CS}_DUT_LVLS: U14.13(B2) U15.3(2B1)
FTDI_CSb_SHIFT: R53.1 U14.4(A2) ; port FTDI_CSb_SHIFT
FTDI_I2C_SCL: U13.7(S2B) ; port FTDI_I2C_SCL
FTDI_SCLK_DUT_LVLS: U14.14(B1) U15.16(1B1)
FTDI_SCLK_SHIFT: R52.1 U14.3(A1) ; port FTDI_SCLK_SHIFT
FTDI_SDI_SHIFT: R54.1 U14.6(A4) ; port FTDI_SDI_SHIFT
FTDI_SDIO_DUT_LVLS: R56.2 R57.2 R58.1 U14.12(B3) U15.9(3B1)
FTDI_SDO_SHIFT: U14.5(A3) ; port FTDI_SDO_SHIFT
SCL_I2C: PP6.1 U13.6(D2) ; port SCL_I2C
SCLK_DUT: PP7.1 U15.2(1A) ; port SCLK_DUT
SDA_I2C: PP5.1 U13.10(D1) ; port SDA_I2C
SDIO_DUT: PP9.1 U15.7(3A) ; port SDIO_DUT
SEN_DUT: PP8.1 U15.5(2A) ; port SEN_DUT
USB_I2C_SDAr: U13.9(S1B) ; port FTDI_I2C_SDA
NetR51_1: R51.1 SW2.2(COMM)
NetR55_2: R55.2 U14.11(B4) U16.1(~{OE})
NetR57_1: R57.1 U16.4(Y)
NetR149_1: R149.1 U23.4(Y)
NetSW2_1: SW2.1 U13.1(SEL1) U13.5(SEL2) U15.15(S)

Not connected (* = marked no-connect by the designer): U15 10(4A)* 11(4B2)* 12(4B1)*

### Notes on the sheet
- FTDI → DUT SPI
- FMC → DUT SPI

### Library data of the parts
C44-C47 = capcc09401: as C17 on sheet Power LDO
PP5-PP9 = Probe Point: as PP1 on sheet 12V Input, Efuse and 3p3V Utility
R51-R55 R58-R61 R147 R150 = RSMD040200315: as R5 on sheet 12V Input, Efuse and 3p3V Utility
R56 R148 = RSMD040200011: RES 1K OHM 5% 1/10W 0402 SMD; Manufacturer: Panasonic Electronic Components; CompType: Resistor SMD; Power (Watts): 0.1W, 1/10W; Temperature Coefficient: ±200ppm/°C; SizeX_mm: 1; SizeY_mm: 0.5; SizeZ_mm: 0.4
R57 R149 = RSMD040200375: as R40 on sheet USB Control FTDI
SW2 = cmp00353: Switch Slide SPDT 12V, 500mA; Manufacturer: Wurth Elektronik
U13 = cmp00307: 5-V low-leakage-current, 2: 1, 2-channel precision analog switch; PartNumber: TMUX1136DQA; Manufacturer: Texas Instruments; CompType: MUX
U14 = cmp00170: Translation - Voltage Levels 4-bit dual-supply bus transceiver with 3-state outputs and independent direction control inputs; Manufacturer: Texas Instruments; Alt PartNumber: SN74AXC4T774BQB; CompType: Level Shifter
U15 = SN74CBTLV3257RSV: Low-Voltage 4-Bit 1-of-2 FET Multiplexer/Demultiplexe; PartNumber: SN74CBTLV3257RSVR; Manufacturer: Texas Instruments; UniqueID: cmp00269; CompType: MUX
U16 U23 = SN74LVC1G125DRL: Single Bus Buffer Gate With 3-State Outputs. Active low enable.; Manufacturer: Texas Instruments

## Sheet CLK and DCLKIN.SchDoc: CLK & DCLKIN
size 431 x 279 mm; Date: Not shown in title block; ApprovedBy: Not shown in title block; CheckedBy: Not shown in title block; Author: Not shown in title block; CompanyName: Not shown in title block; Engineer: Not shown in title block; Organization: Not shown in title block; Address1: Not shown in title block; Address2: Not shown in title block; Address3: Not shown in title block; Address4: Not shown in title block; DocumentNumber: 1; Revision: Use project parameter SCH_Rev; SheetNumber: 8; SheetTotal: 14; PageSetup: Record=PageOptions¦CenterHorizontal=True¦CenterVertical=True¦PrintScale=1.00¦XCorrection=1.00¦YCorrection=1.00¦PrintKind=0¦BorderSize=5000000¦LeftOffset=0¦BottomOffset=0¦Orientation=2¦PaperLength=1000¦PaperWidth=1000¦Scale=100¦PaperSource=15¦PrintQuality=600¦MediaType=1¦DitherType=10¦PaperKind=Letter¦PrintScaleMode=1
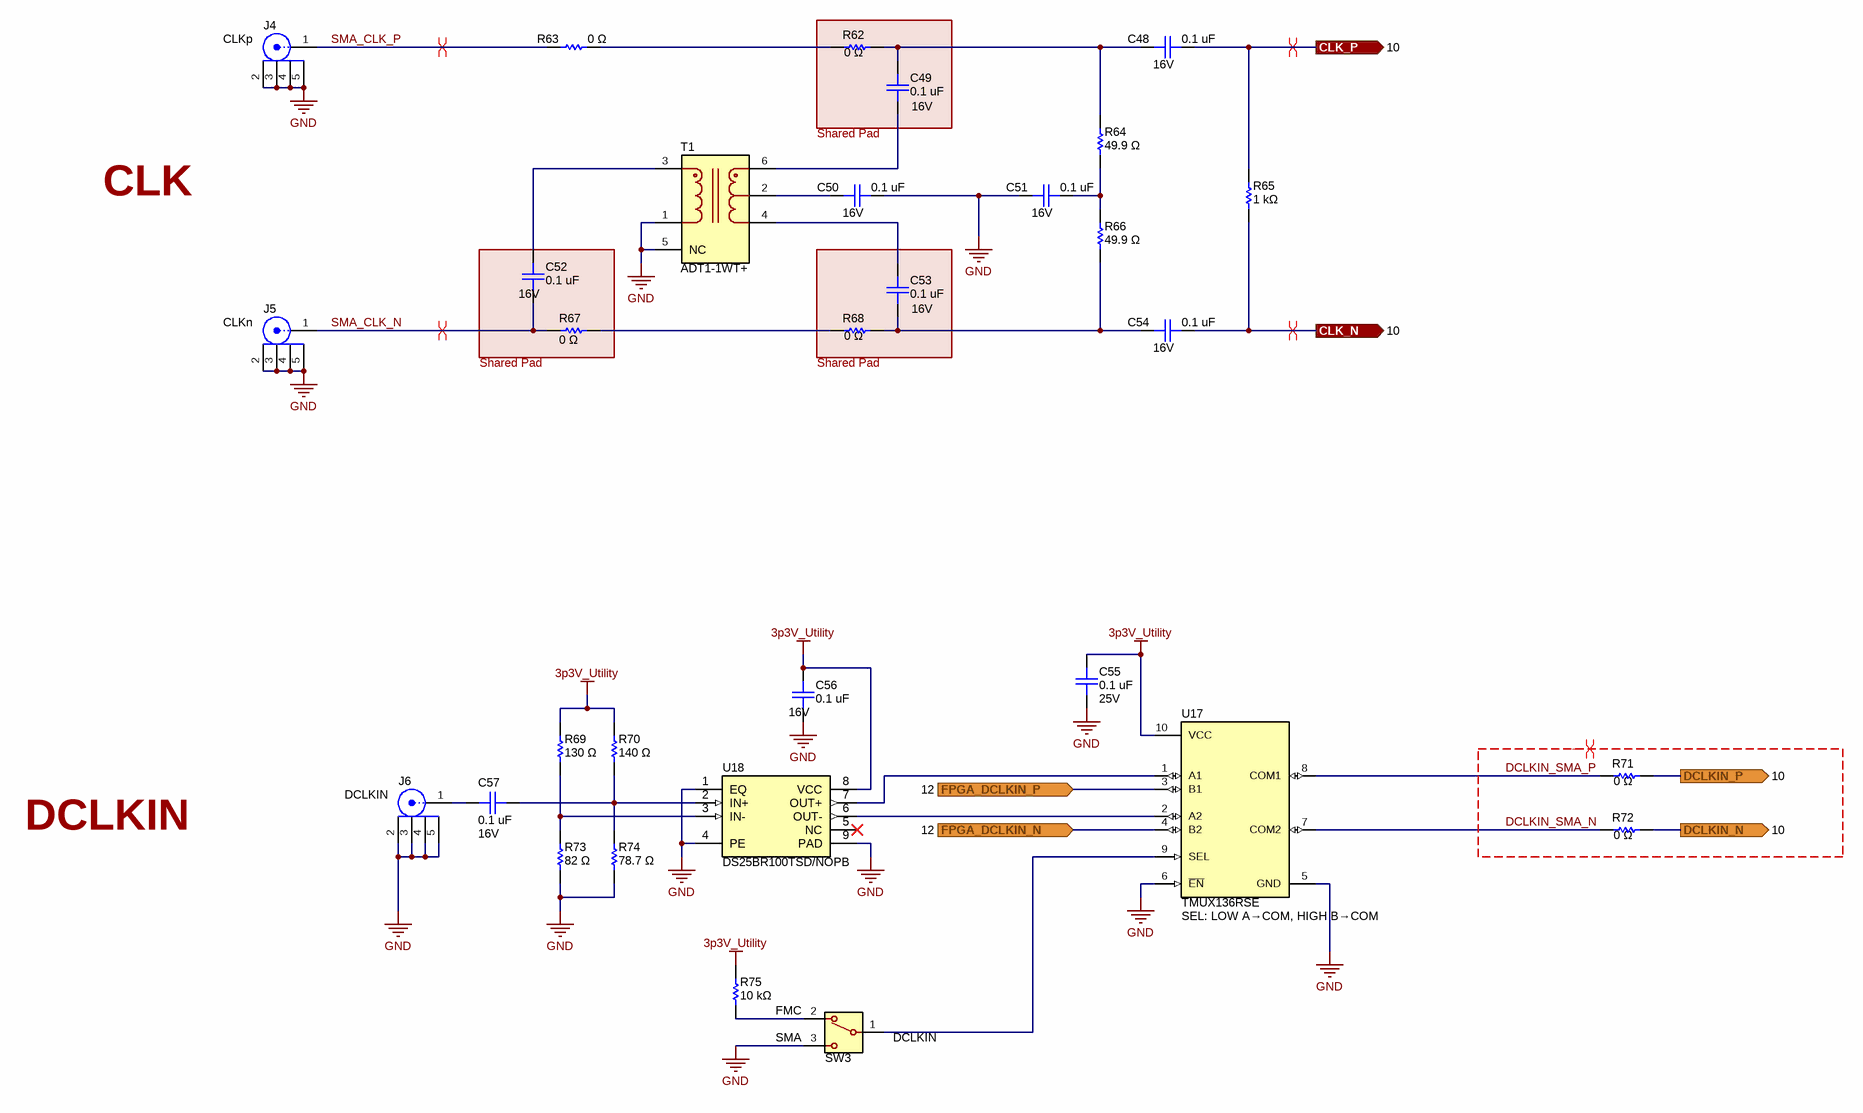
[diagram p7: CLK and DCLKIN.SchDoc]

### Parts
(Parts that share a designator on the sheet are numbered #1, #2 ... from top to bottom, then left to right.)
?#1  Shared Pad  (graphical)
?#2  Shared Pad  (graphical)
?#3  Shared Pad  (graphical)
C48  value 0.1 uF  Voltage - Rated: 16V  [0201_cap]  (hidden comment: GRM033Z71C104ME14D)
C49  value 0.1 uF  Voltage - Rated: 16V  [0201_cap]  (hidden comment: GRM033Z71C104ME14D)
C50  value 0.1 uF  Voltage - Rated: 16V  [0201_cap]  (hidden comment: GRM033Z71C104ME14D)
C51  value 0.1 uF  Voltage - Rated: 16V  [0201_cap]  (hidden comment: GRM033Z71C104ME14D)
C52  value 0.1 uF  Voltage - Rated: 16V  [0201_cap]  (hidden comment: GRM033Z71C104ME14D)
C53  value 0.1 uF  Voltage - Rated: 16V  [0201_cap]  (hidden comment: GRM033Z71C104ME14D)
C54  value 0.1 uF  Voltage - Rated: 16V  [0201_cap]  (hidden comment: GRM033Z71C104ME14D)
C55  value 0.1 uF  Voltage - Rated: 25V  [0402L_cap]  (hidden comment: GRT155R71E104KE01J)
C56  value 0.1 uF  Voltage - Rated: 16V  [0201_cap]  (hidden comment: GRM033Z71C104ME14D)
C57  value 0.1 uF  Voltage - Rated: 16V  [0201_cap]  (hidden comment: GRM033Z71C104ME14D)
J4  Text1: CLKp  [FP-132134-15_CONN_SMA_JACK-MFG]  (hidden comment: 132134-15)
J5  Text1: CLKn  [FP-132134-15_CONN_SMA_JACK-MFG]  (hidden comment: 132134-15)
J6  Text1: DCLKIN  [FP-132134-15_CONN_SMA_JACK-MFG]  (hidden comment: 132134-15)
R62  value 0 Ω  [0201]  (hidden comment: ERJ-1GN0R00C)
R63  value 0 Ω  [0201]  (hidden comment: ERJ-1GN0R00C)
R64  value 49.9 Ω  [0201]  (hidden comment: ERJ-1GNF49R9C)
R65  value 1 kΩ  [0201]  (hidden comment: ERJ-1GNF1001C)
R66  value 49.9 Ω  [0201]  (hidden comment: ERJ-1GNF49R9C)
R67  value 0 Ω  [0201]  (hidden comment: ERJ-1GN0R00C)
R68  value 0 Ω  [0201]  (hidden comment: ERJ-1GN0R00C)
R69  value 130 Ω  [0201]  (hidden comment: ERJ-1GNF1300C)
R70  value 140 Ω  [0201]  (hidden comment: ERJ-1GNF1400C)
R71  value 0 Ω  [0201]  (hidden comment: ERJ-1GN0R00C)
R72  value 0 Ω  [0201]  (hidden comment: ERJ-1GN0R00C)
R73  value 82 Ω  [0201]  (hidden comment: ERJ-1GNF82R0C)
R74  value 78.7 Ω  [0201]  (hidden comment: ERJ-1GNF78R7C)
R75  value 10 kΩ  [0402L]  (hidden comment: ERA-2AEB103X)
SW3  Text1: DCLKIN  Text2: FMC  Text3: SMA  [450301014042]  (hidden comment: cmp00353)
T1  ADT1-1WT+  [CD542]
U17  TMUX136RSE  Text1: SEL: LOW A→COM, HIGH B→COM  [RSE0010A]
U18  DS25BR100TSD/NOPB  [NGQ0008A]

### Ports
CLK_N (out, see 10), CLK_P (out, see 10), DCLKIN_N (out, see 10), DCLKIN_P (out, see 10), FPGA_DCLKIN_N (in, see 12), FPGA_DCLKIN_P (in, see 12)

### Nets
3p3V_Utility: C55.2 C56.2 R69.2 R70.2 R75.2 U17.10(VCC) U18.8(VCC)
GND: C50.2 C51.1 C55.1 C56.1 J4.2 J4.3 J4.4 J4.5 J5.2 J5.3 J5.4 J5.5 J6.2 J6.3 J6.4 J6.5 R73.1 R74.1 SW3.3 T1.1(PRIMARY) T1.5(NC) U17.5(GND) U17.6(~{EN}) U18.1(EQ) U18.4(PE) U18.9(PAD)
CLK_N: C54.2 R65.1 ; port CLK_N
CLK_P: C48.2 R65.2 ; port CLK_P
DCLKIN_N: R72.2 ; port DCLKIN_N
DCLKIN_P: R71.2 ; port DCLKIN_P
DCLKIN_SMA_N: R72.1 U17.7(COM2)
DCLKIN_SMA_P: R71.1 U17.8(COM1)
FPGA_DCLKIN_N: U17.4(B2) ; port FPGA_DCLKIN_N
FPGA_DCLKIN_P: U17.3(B1) ; port FPGA_DCLKIN_P
SMA_CLK_N: C52.2 J5.1 R67.1
SMA_CLK_P: J4.1 R63.1
NetC48_1: C48.1 C49.2 R62.2 R64.2
NetC49_1: C49.1 T1.6(SECONDARY_DOT)
NetC50_1: C50.1 T1.2(SECONDARY_CT)
NetC51_2: C51.2 R64.1 R66.2
NetC52_1: C52.1 T1.3(PRIMARY_DOT)
NetC53_1: C53.1 C54.1 R66.1 R68.2
NetC53_2: C53.2 T1.4(SECONDARY)
NetC57_1: C57.1 R70.1 R74.2 U18.2(IN+)
NetC57_2: C57.2 J6.1
NetR62_1: R62.1 R63.2
NetR67_2: R67.2 R68.1
NetR69_1: R69.1 R73.2 U18.3(IN-)
NetR75_1: R75.1 SW3.2(COMM)
NetSW3_1: SW3.1 U17.9(SEL)
NetU17_1: U17.1(A1) U18.7(OUT+)
NetU17_2: U17.2(A2) U18.6(OUT-)

Not connected (* = marked no-connect by the designer): U18 5(NC)*

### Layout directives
differential pair; net class DiffPairIN: CLK_N, CLK_P
differential pair: DCLKIN_SMA_N, DCLKIN_SMA_P, SMA_CLK_N, SMA_CLK_P

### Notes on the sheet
- CLK
- DCLKIN

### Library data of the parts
?#1-?#3 = Swizzle: Schematic notation to show that the pads of two components should be overlapped
C48-C54 C56 C57 = capcc09270: CAP CER 0.1UF 16V X7R 0201; Manufacturer: Murata Electronics; CompType: Capacitor Ceramic; Tolerance: ±20%; SizeX_mm: 0.6; SizeY_mm: 0.3; SizeZ_mm: 0.33
C55 = capcc09401: as C17 on sheet Power LDO
J4-J6 = 132134-15: SMA Connector Jack, Female Socket 50Ohm Surface Mount, Through Hole Solder; Manufacturer: Amphenol RF; UniqueID: cmp00028; CompType: RF Connector
R62 R63 R67 R68 R71 R72 = RSMD020101699: as R36 on sheet USB Control FTDI
R64 R66 = RSMD020100177: RES SMD 49.9 OHM 1% 1/20W 0201; Manufacturer: Panasonic Electronic Components; CompType: Resistor SMD; Power (Watts): 0.05W, 1/20W; Temperature Coefficient: ±200ppm/°C
R65 = RSMD020100143: RES SMD 1K OHM 1% 1/20W 0201; Manufacturer: Panasonic Electronic Components; CompType: Resistor SMD; Power (Watts): 0.05W, 1/20W; Temperature Coefficient: ±200ppm/°C
R69 = RSMD020100121: RES SMD 130 OHM 1% 1/20W 0201; Manufacturer: Panasonic Electronic Components; CompType: Resistor SMD; Power (Watts): 0.05W, 1/20W; Temperature Coefficient: ±200ppm/°C
R70 = RSMD020100157: RES SMD 140 OHM 1% 1/20W 0201; Manufacturer: Panasonic Electronic Components; CompType: Resistor SMD; Power (Watts): 0.05W, 1/20W; Temperature Coefficient: ±200ppm/°C
R73 = RSMD020100277: RES SMD 82 OHM 1% 1/20W 0201; Manufacturer: Panasonic Electronic Components; CompType: Resistor SMD; Power (Watts): 0.05W, 1/20W; Temperature Coefficient: ±200ppm/°C
R74 = RSMD020100049: RES SMD 78.7 OHM 1% 1/20W 0201; Manufacturer: Panasonic Electronic Components; CompType: Resistor SMD; Power (Watts): 0.05W, 1/20W; Temperature Coefficient: ±200ppm/°C
R75 = RSMD040200315: as R5 on sheet 12V Input, Efuse and 3p3V Utility
SW3 = cmp00353: as SW2 on sheet Comms LVL Shift and MUX
T1 = ADT1-1WT+: RF Transformer, 75 ohm, 1: 1, 0.4-800MHz, SMT; Manufacturer: Mini-Circuits; AEC Qualified: No; Return Loss: 9.75dB; Insertion Loss: 0.68-2.44dB; SizeZ_mm: 2.84mm
U17 = cmp00385: 1.4-pF on-state capacitance, 5-V, 2:1 (SPDT), 2-channel analog switch with powered-off protection; PartNumber: TMUX136RSER; Manufacturer: Texas Instruments
U18 = DS25BR100TSD/NOPB: 3.125-Gbps LVDS buffer with transmit pre-emphasis and receive equalization; Manufacturer: Texas Instruments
